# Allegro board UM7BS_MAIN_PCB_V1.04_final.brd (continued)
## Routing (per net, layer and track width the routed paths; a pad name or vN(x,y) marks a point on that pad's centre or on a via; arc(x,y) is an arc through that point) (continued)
+V3.3S_MSATA: length 25
  LAY3 w0.762: v2(70.73,33.09) 74.73,37.08 74.73,54.17 76.15,55.59 v2(76.41,55.59)
+V5_AVDD: length 25.3
  LAY3 w0.305: v1(24.9,24.75) 26.86,22.78 v1(33.87,22.78)
  LAY3 w0.406: v1(24.9,24.75) 20.82,24.75 19.86,25.71 v1(19.86,26.75)
  BOTTOM w0.178: 20.96,32.48 21.52,33.04 U25.26
  BOTTOM w0.254: R355.2 v1(33.87,22.78)
  BOTTOM w0.305: R349.2 v1(24.9,24.75)
  BOTTOM w0.406: C370.1 20.54,31.33 C369.2 20.96,31.47 20.96,32.48
  BOTTOM w0.508: C370.1 19.6,28.92 FB8.1 19.62,27.54 D43.N v1(19.86,26.75)
+V5_PVDD: length 8.5
  LAY3 w0.406: v1(24.38,39.02) 24.84,38.56 27.84,38.56 v1(28.15,38.87)
  BOTTOM w0.178: U25.41 24.23,38.44 ; U25.46 26.23,38.02 27.02,38.82 27.02,38.91
  BOTTOM w0.254: 24.23,38.44 23.76,38.91 23.76,39.32 24.03,39.6 C382.2
  BOTTOM w0.406: C382.2 24.38,39.29 v1(24.38,39.02)
+V5A: length 202.8
  TOP w0.178: U11.24 160.84,17.78 ; U11.11 156.63,21.19 ; U11.57 160.84,26.63 ; U11.21 159.64,17.77
  TOP w0.203: R174.1 181.89,95.57 v1(182.24,95.92) ; R492.1 60.95,11.85 ; 41.26,19.8 41.26,20.73 41.62,21.09 41.62,21.94 41.11,22.45 R487.1
  TOP w0.254: v1(147.22,47.73) 147.34,47.61 C11.2 150.99,47.27 151.63,46.62 U3.4 ; v1(138.46,54.12) 138.92,54.59 150.43,54.59 151.38,55.54 v1(151.38,56.05)
  TOP w0.305: 156.63,21.19 156.35,21.19 ; v1(160.91,16.95) 160.84,17.03 160.84,17.78 ; 160.84,26.63 v1(160.66,26.81) ; v1(167.41,90.98) 167.41,90.56 R171.2 ; R177.1 v1(168.18,92.56) ; 159.64,17.77 v1(159.64,16.98)
  TOP w0.508: v1(124.62,56.86) 136.67,56.86 137.79,57.98 137.79,71.86 137,72.65
  LAY3 w0.305: v1(122.54,65.38) 123.56,65.38 125.41,67.23 130.57,67.23 v1(133.77,70.43) ; v2(135.75,75.36) 136.87,75.36 138.31,76.8 151.11,76.8 v1(152.26,75.64)
  LAY4 w0.305: 136.15,74.22 136.58,73.79 136.58,63.29 139.44,60.43 139.44,55.8 145.91,49.33 145.91,48.78 146.96,47.73 v1(147.22,47.73)
  BOTTOM w0.203: U10.14 121.6,63.47 122.54,64.41 v1(122.54,65.38)
  BOTTOM w0.254: v1(152.26,75.64) 152.26,74.94 152.75,74.46 158.31,74.46 159.88,72.89 159.88,71.34 161.08,70.14 161.9,70.14 C2836.1 163.25,68.79 163.38,68.79 ; v1(138.46,54.12) 138.46,54.44 135.98,56.92
  BOTTOM w0.305: v1(151.38,56.05) C436.1 151.38,53.77 U53.10 ; v1(152.26,75.64) 152.95,76.32 155.69,76.32 161.25,81.89 161.88,81.89 164.72,84.73 164.72,88.29 v1(167.41,90.98) 167.41,91.78 v1(168.18,92.56) 171.54,95.92 v1(182.24,95.92) ; 163.38,68.79 U2525.10
  BOTTOM w0.381: v1(160.66,26.81) 160.08,26.24 C218.1 158.01,26.06 157.83,26.24 157.04,26.24 156.76,25.96 156.76,23.22 156.17,22.63 155.71,22.63 155.33,22.25 155.33,21.03 ; 107.43,59.94 D4.1 107.43,64.76 C180.1
  BOTTOM w0.508: R180.1 124.51,56.97 v1(124.62,56.86)
  vias: v1(155.25,19.95) v1(155.63,20.36) v1(156.04,20.77) v1(159.64,16.34) v1(160.91,16.34) v2(13.19,80.45) v2(14.08,80.45) v2(41.23,16.09) v2(45.85,37.42) v2(46.61,37.42) v2(47.37,37.42) v2(53.05,87.7) v2(53.81,87.7) v2(61.22,11.11) v2(133.97,76.63) v2(133.97,75.36) v2(134.86,76.63) v2(134.86,75.36) v2(135.75,76.63) v2(143.76,21.43) v2(143.77,22.39) v2(144.53,22.39) v2(144.53,21.43)
+V5A_LDO: length 41.7
  TOP w0.178: C182.2 160.13,27.67 160.67,27.67 161.24,27.11 U11.56 ; v1(154.84,22.47) 154.89,22.52 156,22.52 156.13,22.39 U11.8 ; U11.38 166.23,21.19
  TOP w0.203: 166.23,21.19 166.46,20.96 166.82,20.96 v1(167.04,20.74)
  TOP w0.508: C182.2 159.05,28.09 v1(159.05,27.7)
  LAY4 w0.508: v1(168.88,27.42) 167.8,27.42 164.3,23.92 160.32,23.92 158.94,25.29 158.94,27.59 v1(159.05,27.7)
  BOTTOM w0.381: v1(159.05,27.7) 159.05,28.2 158.78,28.48 156.85,28.48 154.64,26.26 154.64,23.94 154.2,23.5 C212.2 154.79,22.52 v1(154.84,22.47)
  BOTTOM w0.508: v1(167.04,20.74) C215.1 168.08,21.11 168.08,22.89 168.88,23.69 v1(168.88,27.42)
+V5S: length 91.6
  TOP w0.381: R2.1 132.94,13.08 132.68,13.34 FB24.2
  TOP w0.508: v2(134.55,17.31) 134.55,16.58 132.68,14.71 FB24.2
  LAY3 w0.203: v1(42.71,66.55) 42.71,68.92 45.89,72.1 45.89,76.62 50.91,81.65 v1(51.73,81.65)
  LAY4 w0.508: v2(138.65,42.35) 136.86,40.56 136.86,33.33 134,30.47 134,24.9 133.08,23.99 133.08,18.77 v2(134.55,17.31)
  BOTTOM w0.203: v1(42.71,66.55) 43.01,66.85 R418.1 R419.1
  BOTTOM w0.305: 110.67,82.98 R223.1 R225.1
  BOTTOM w0.508: 139.82,69.46 139.29,68.93 139.29,65.51 137.93,64.14 137.93,59.33 139.1,58.16 139.1,42.8 v2(138.65,42.35) ; FB8.2 18.12,28.06 D43.P 17.36,26.4 C360.1 18.01,25.07 v1(17.74,24.8)
  vias: v2(30.41,45.27) v2(30.91,83.21) v2(31.8,83.21) v2(89.59,67.32) v2(90.64,67.32) v2(106.29,84.04) v2(107.05,84.04) v2(141.24,84.8) v2(141.24,84.04) v2(142,84.8) v2(142,84.04) v2(150.55,71.85) v2(150.55,70.96) v2(150.55,70.07) v2(151.31,71.85) v2(151.31,70.96) v2(151.31,70.07)
+V5S_HDD:
  vias: v2(98.42,54.95) v2(99.31,54.97)
+V15A: length 79.3
  TOP w0.305: v1(109.18,76.33) 108.59,75.75 108.59,73.12 108.89,72.82 v1(108.89,65.79)
  BOTTOM w0.305: v1(108.89,65.79) 112.19,65.79 C179.1 ; C179.1 116.02,65.1 117.21,66.3 117.21,71.15 121.48,75.41 129.97,75.41 131.98,77.43 146.96,77.43 150.47,73.92 155.85,73.92 156.62,73.15 R215.1 158.93,71.89 R216.1 ; C179.1 D5.2 ; R221.1 113.06,74.94 R220.1 112.66,74.93 112.54,75.05 111.2,75.05 110.48,75.77 109.74,75.77 v1(109.18,76.33)
+VCCCFIOAZA: length 6.8
  BOTTOM w0.381: v1(184.65,51.25) 184.67,51.25 C112.1 185.51,50.71 186.21,50.02 186.21,48.32 185.68,47.8 R137.2 R138.2
+VCCDPYCSIAON_1P24: length 11.2
  LAY4 w0.305: v1(178.79,69.17) 178.45,69.17 178.01,69.62 177.55,69.62 177.26,69.33 176.24,69.33 v1(176.17,69.41)
  BOTTOM w0.381: v1(178.79,69.17) 178.96,69.17 179.44,69.66 C81.2 179.47,70.05 R130.2 ; v1(176.17,69.41) 176.17,68.39 175.48,67.71 175.48,66.46 175.73,66.21 177.88,66.21 R136.2
+VCCPADHSICAON_1P24: length 2.2
  TOP w0.203: v1(177.77,69.03) 177.77,69.08 U1.M41
  BOTTOM w0.381: R139.2 177.77,68.8 v1(177.77,69.03) 177.77,69.22 R131.2
+VCCPADSSICAON_1P24: length 4.1
  TOP w0.203: U1.P41 178.63,69.81 v1(178.79,69.81)
  BOTTOM w0.381: R142.2 178.45,72.3 178.45,71.72 R132.2 178.06,70.54 v1(178.79,69.81)
+VDDI_EMMC: length 6.2
  BOTTOM w0.076: 179.46,31.52 179.46,30.88 U8.K2 179.96,30.86 179.96,31.53
  BOTTOM w0.381: C143.1 182.09,34.48 179.68,32.06 179.68,31.81
AGND: length 175.4
  TOP w0.203: v1(18.15,33.19) 17.89,33.45 17.89,35.83 18.2,36.15 18.74,36.15 19.38,35.51 19.38,34.28 v1(21.66,32) 23.63,32 24.09,31.53 32.15,31.53 33.95,29.72 37.11,29.72 37.63,29.2 37.63,27.53 36.8,26.7 35.87,26.7 35.4,27.17 30.98,27.17 30.04,26.24 J3.5 ; v1(24.32,25.87) 24.32,25.87 23.57,25.87 22.98,25.28 21.74,25.28 21.29,25.73 21.29,26.22 20.19,27.33
  TOP w0.254: C397.2 24.66,28.62 24.91,28.37 26.29,28.37 26.55,28.62 v1(26.55,28.7)
  TOP w0.305: C397.2 24.65,28.7 R357.2 ; C399.2 21.95,25.87 v1(22.01,25.81) ; CN7.E2 59.84,8.14 58.54,9.44 CN7.1 58.54,11.17 58.28,11.43 54.91,11.43 51.83,8.35 33.61,8.35 26.27,15.69 26.27,26.46 v1(26.14,26.59) 26.16,26.6 26.16,27.04 25.84,27.36 25.3,27.36 24.92,26.99 24.92,25.88 ; v1(18.15,33.19) 20.59,30.75 v1(20.59,29.72) 20.19,29.32 20.19,27.33 ; C398.2 32.27,29.25 J3.2 ; 24.92,25.88 25.4,25.4 25.4,15.33 33.25,7.48 52.19,7.48 54.62,9.91 56.47,9.91 57.05,9.34 57.05,8.69 B1.2 ; 24.92,25.88 24.34,25.88 v1(24.32,25.87) ; R356.2 22.87,30.15 C396.2 22.87,30.22 22.23,30.86 v1(21.95,30.86)
  BOTTOM w0.178: U25.38 23.03,38.04 22.71,38.36 22.05,38.36 v1(21.94,38.25) ; v1(21.66,32) 21.65,32 21.44,32.2 21.44,32.46 21.63,32.64 U25.25
  BOTTOM w0.305: Q36.2 v1(27.69,25.03) ; R338.2 26.7,28.86 v1(26.55,28.7) ; C376.1 18.2,41.39 v1(17.63,40.81) ; C393.2 v1(30.29,19.88) ; C394.2 v1(37.5,19.41)
  BOTTOM w0.381: C370.2 v1(18.4,30.39) ; v1(20.83,41.22) 20.83,41.16 21.47,40.52 C372.2 22.2,39.5 C371.1 ; C369.1 20.82,29.96 v1(20.59,29.72) ; C365.1 18.44,32.9 v1(18.15,33.19) 18.14,33.2 C363.2
  vias: v1(20.4,43.12) v1(20.41,42.58) v1(23.73,25.42)
AVDD2: length 5.4
  BOTTOM w0.178: 23.83,38.23 U25.40
  BOTTOM w0.254: 23.83,38.23 23.15,38.91 C371.2
  BOTTOM w0.381: C371.2 23.15,40.05 C372.1
  BOTTOM w0.508: C372.1 22.99,40.25 FB11.1 FB10.1
AVDD33: length 3.8
  BOTTOM w0.203: U95.4 76.81,94.37 C702.2
  BOTTOM w0.305: FB20.1 77.36,91.62 C703.1 77.36,92.82 C702.2
AVDD33_REG: length 8.7
  BOTTOM w0.203: U22.34 124.3,37.2 124.51,37 124.51,36.8 U22.35
  BOTTOM w0.381: C336.1 125.37,35.94 124.51,36.8
  BOTTOM w0.508: C336.1 125.92,35.65 126.27,35.29 128.17,35.29 128.55,35.67 C335.2 R299.1
GND: length 1635.2
  TOP w0.102: v1(195.34,76.1) 194.88,75.8 U1.BG53
  TOP w0.152: 178.96,64.88 U1.U32 ; U1.U32 179.35,65.28 ; U1.U32 179.67,64.88 ; 185.12,69.92 U1.AH42 ; U1.AH42 184.73,70.23 ; U1.AH42 185.12,70.53 ; U1.AH42 185.42,70.23 ; 184.06,61.49 U1.AF24 183.74,61.09 ; U1.U29 179.35,63.76 ; U1.U29 179.67,63.37 ; U1.U29 178.96,63.37 ; 181,51.7 U1.Y4 ; U1.Y4 181.53,51.47 ; U1.Y4 180.85,51.47 ; U1.AN29 187.98,63.77 U1.AN30 ; U1.AN29 187.98,63 ; U1.AN29 187.66,63.37 ; 187.98,68.23 U1.AN38 188.3,67.92 ; 185.12,69.13 U1.AH41 ; U1.AH41 184.73,69.51 ; U1.AH41 185.31,69.51 185.41,69.62 ; U1.AH41 185.12,69.82 ; 188.03,53.19 U1.AP9 ; U1.AP9 188.03,53.95 ; U1.AP9 188.33,53.57 ; 191,60.78 U1.AY24 ; U1.AY24 190.62,61.16 ; U1.AY24 191.3,61.16 ; 175.25,64.06 U1.J30 ; U1.J30 175.93,64.06 ; U1.J30 175.63,64.44 ; 178.47,64.67 U1.P32 ; U1.P32 178.09,65.05 ; U1.P32 178.47,65.43 ; U1.P32 178.78,65.05 ; U1.AE48 183.97,72.72 ; U1.A5 171.52,51.44 ; U1.A5 171.85,51.77 ; U1.A5 171.85,51.11 ; 175.63,69.54 U1.J42 ; U1.J42 175.25,69.92 ; U1.J42 175.63,70.31 ; U1.J42 175.93,69.92 ; 180.55,69.65 180.42,69.51 U1.V41 180.26,69.81 ; 185.42,54.28 U1.AH10 185.12,54.66 ; 179.38,71.98 179.76,71.98 U1.U46 179.79,72 180.14,72 ; 180.92,60.73 U1.Y22 181.24,60.33 ; 186.41,51.47 U1.AK4 185.73,51.47 ; 181.23,56.03 U1.Y14 ; U1.Y14 181.23,56.79 ; U1.Y14 181.53,56.41 ; U1.Y14 180.85,56.41 ; U1.AH44 184.81,70.94 ; U1.AH44 185.12,70.63 ; U1.AH44 185.12,71.24 ; 176.9,68.93 U1.M40 ; U1.M40 176.82,68.54 ; U1.M40 177.22,68.65 ; U1.M40 177.62,68.54 ; 191.97,74.17 U1.BB50 191.67,73.87 ; 180.52,62.96 U1.Y29 ; U1.Y29 181.33,62.96 ; U1.Y29 180.92,63.06 ; 189.13,50.54 U1.AU3 ; U1.AU3 189.79,50.54 ; U1.AU3 189.5,50.91 ; U1.AN30 188.3,64.12 ; U1.AN30 U1.AM30 187.2,64.52 ; U1.AN30 187.98,64.46 ; U1.AC29 182.81,63.37 ; U1.AC29 182.49,63.76 ; U1.AC29 182.1,63.37 ; U1.AC29 182.49,62.97 ; 185.12,55.37 U1.AH12 185.42,54.99 ; U1.Y45 181.53,71.65 ; U1.Y45 181.23,72.03 ; U1.Y45 181.23,71.27 ; U1.U38 179.67,67.92 ; U1.U38 179.35,68.31 ; U1.U38 178.96,67.92 ; 195.48,54.55 U1.BJ11 ; U1.BJ11 195.48,55.11 ; U1.BJ11 v1(196.11,54.83) ; 180.53,59.57 U1.Y21 ; U1.Y21 181.24,59.57 ; U1.Y21 180.92,59.97 ; U1.Y21 180.92,59.18 ; 181.72,75.02 U1.AA53 ; U1.AA53 182.08,75.42 ; U1.AA53 181.72,75.82 ; U1.T47 179.31,72.74 ; U1.T47 179.31,71.98 ; U1.T47 179,72.36 ; U1.BG49 194.31,73.49 ; U1.BG49 194,73.19 ; U1.BG49 194.31,72.88 ; U1.BC16 192.42,57.65 ; U1.BC16 192.04,57.27 ; U1.BC16 192.72,57.27 ; U1.BC16 192.42,56.89 ; U1.A7 171.52,52.86 ; U1.AM50 187.05,73.44 ; U1.AM50 186.75,73.74 ; U1.AM50 187.3,73.99 187.81,73.99 U1.AP50 188.12,73.74 v1(188.49,74.11) ; 179.78,68.87 U1.U40 ; 173.19,54.3 173.19,54.3 U1.D10 173.8,54.3 ; U1.AB47 182.6,72.36 ; U1.AB47 182.22,72.03 ; U1.AB47 182.22,72.74 ; U1.M45 177.65,71.65 ; U1.M45 177.34,71.27 ; U1.M45 176.96,71.65 ; U1.M45 177.34,72.03 ; 182.22,56.08 U1.AB13 182.52,55.7 ; U1.P22 178.47,60.55 ; U1.P22 178.78,60.17 ; U1.P22 U1.N22 178.16,60.57 ; U1.BG38 194.4,68.24 ; U1.BG38 194.4,67.66 ; U1.BG38 194.69,67.95 ; U1.BF32 193.8,65.35 ; 179.82,64.88 U1.V32 180.14,64.49 ; U1.AM38 187.38,67.92 187.5,68.04 ; U1.AM38 187.2,68.23 ; U1.AM38 187.05,67.92 186.9,68.07 ; 191.59,51.35 U1.BB4 ; U1.BB4 191.97,51.73 ; U1.BB4 192.28,51.35 ; U1.U25 179.76,61.44 ; U1.U25 179.04,61.85 ; U1.U25 178.95,62.25 ; U1.U25 178.95,61.44 ; U1.AY45 191.29,71.65 ; U1.AY45 190.98,71.34 ; U1.AY45 190.98,71.95 ; U1.T14 179.61,56.41 ; U1.T14 179.31,56.03 ; U1.T14 178.92,56.41 ; U1.T14 179.31,56.79 ; 193.8,60.55 U1.BF22 193.5,60.17 ; v1(182.88,59.2) 183.26,59.57 U1.AD21 182.87,59.17 ; 193.97,63.07 U1.BF28 193.66,62.77 ; 186.8,61.09 U1.AM24 ; U1.AM24 187.2,61.49 ; U1.AM24 187.51,61.09 ; U1.AM24 187.2,60.7 ; 186.01,62.2 U1.AK27 ; U1.AK27 186.82,62.2 ; U1.AK27 186.82,63.01 ; U1.AJ25 185.63,62.24 ; U1.AJ25 185.23,61.85 ; U1.AJ25 185.63,61.46 ; 172.24,66.61 U1.B36 ; U1.B36 172.53,66.98 ; U1.B36 172.24,67.35 ; U1.B36 171.87,66.98 ; 181.82,73.35 U1.AB50 ; U1.AB50 181.82,74.14 ; U1.AB50 182.62,73.35 ; 178.42,58.72 U1.P19 178.12,58.34 ; 176.75,69.04 U1.L41 176.75,69.74 ; 186.14,68.19 U1.AK38 186.45,67.92 186.69,68.15 ; U1.BG47 194.38,72.47 ; U1.BG47 194.38,71.86 ; U1.BG47 194.07,72.16 ; 182.81,51.22 U1.AD4 ; U1.AD4 182.81,52.01 ; U1.AD4 183.2,51.28 ; U1.AD4 183.51,51.61 ; U1.AD4 182.88,51.61 ; 186.41,73.74 U1.AK50 186.11,73.44 ; U1.AW35 190.64,66.19 ; v1(173.25,66.49) 173.25,66.49 U1.E35 173.85,66.87 ; U1.AJ16 185.63,57.69 ; U1.AJ16 185.23,57.3 ; U1.AJ16 185.95,57.3 ; U1.AJ16 185.63,56.91 ; 195.08,62.61 U1.BJ27 ; U1.BJ27 195.81,62.61 ; U1.BJ27 195.48,62.3 ; U1.AE43 183.64,70.61 183.33,70.61 ; U1.AB14 182.22,56.79 ; U1.AB14 181.84,56.41 ; U1.AB14 182.52,56.41 ; 174.56,66.84 U1.F35 174.56,66.17 ; U1.AF47 184.14,72.67 ; U1.AF47 184.14,72.05 ; U1.AF47 184.45,72.36 ; 172.89,68.44 U1.C39 172.6,68.07 ; U1.AF25 184.06,62.24 ; 190.64,58.42 U1.AW19 190.64,59.08 ; 194.74,62.24 U1.BG27 ; U1.BG27 194.37,62.61 ; U1.BG27 195.03,62.61 ; 191.3,62.13 U1.AY26 191.39,61.74 ; 179.68,59.45 179.56,59.57 U1.U21 ; U1.AN1 187.83,49.79 ; U1.AN1 187.55,49.39 ; U1.AN1 187.55,50.19 ; U1.AN1 187.2,49.79 ; U1.AK44 186.41,70.94 ; U1.AK44 185.8,70.94 ; U1.AK44 186.11,70.63 ; U1.AK44 186.11,71.24 ; U1.AY22 191,60.55 ; U1.AY22 191,59.79 ; U1.AY22 191.3,60.17 ; U1.AY22 190.62,60.17 ; 177.76,64.67 U1.N32 ; U1.N32 178.07,65.05 ; U1.N32 177.76,65.43 ; U1.N32 177.38,65.05 ; 185.23,58.06 U1.AJ18 ; U1.AJ18 185.95,58.06 ; U1.AJ18 185.63,58.45 ; U1.V25 180.54,61.44 ; U1.V25 180.46,61.85 ; U1.V25 180.54,62.25 ; U1.V25 179.73,61.44 ; U1.AC35 182.9,65.99 ; U1.AC35 182.17,66.4 ; U1.AC35 182.09,66.8 ; 182.49,56.91 U1.AC16 182.81,57.3 ; 172.33,49.79 U1.C1 172.72,49.55 172.55,49.39 ; U1.C36 172.65,66.98 ; U1.C36 172.94,66.61 ; U1.C36 172.94,67.35 ; 185.12,53.19 U1.AH9 ; U1.AH9 184.73,53.57 ; U1.AH9 185.12,53.95 ; U1.AH9 185.42,53.57 ; U1.Y10 181.23,54.66 ; U1.Y10 181.53,54.28 ; U1.Y10 180.85,54.28 ; U1.K34 176.64,66.02 ; U1.K34 175.96,66.02 ; U1.K34 176.34,65.64 ; U1.BJ15 v1(196.11,56.78) ; U1.BJ15 195.48,56.5 ; U1.BJ15 195.48,57.09 ; U1.D32 U1.F32 174.51,65.05 ; U1.BG19 195.03,58.72 ; U1.BG19 194.74,59.09 ; U1.BG19 194.74,58.35 ; v1(175.91,64.58) 176.34,64.16 U1.K30 175.96,64.06 ; U1.P42 178.33,70.61 ; U1.P42 178.64,70.23 ; U1.P42 177.95,70.23 ; 181.84,54.28 U1.AB10 ; U1.AB10 182.22,53.9 ; U1.AB10 182.52,54.28 ; U1.AB10 182.22,54.66 ; U1.AT36 188.86,67.28 ; U1.AT36 188.86,66.66 ; U1.AT36 188.56,66.97 ; U1.AB6 182.22,52.53 ; U1.AB6 182.52,52.14 ; U1.AB6 181.84,52.14 ; 188.64,50.88 U1.AT3 ; U1.AT3 189.3,50.88 ; U1.AT3 189.01,50.51 ; U1.J38 175.63,68.32 ; U1.J38 175.93,67.94 ; U1.J38 175.63,67.56 ; U1.J38 175.25,67.94 ; U1.BJ19 195.48,59.02 ; U1.BJ19 v1(195.98,58.72) ; U1.BJ19 195.48,58.39 ; 180.11,51.8 179.79,51.8 U1.U5 ; 172.96,71.78 U1.C47 ; U1.C47 172.96,72.54 ; U1.C47 173.26,72.16 ; U1.J22 175.25,60.54 v1(175.25,60.64) ; U1.G22 174.64,60.44 v1(174.64,60.64) ; U1.AY9 191.29,53.57 ; U1.AY9 190.6,53.57 ; U1.AY9 190.98,53.95 ; U1.AH13 185.12,55.39 ; 174.53,64.06 U1.G30 ; U1.G30 175.22,64.06 ; U1.G30 174.92,63.68 ; U1.G30 174.92,64.44 ; U1.AW13 190.89,55.86 ; U1.AW13 190.58,55.48 ; U1.AW13 190.58,56.24 ; 175.96,65.05 U1.K32 ; U1.K32 176.64,65.05 ; U1.K32 176.34,65.43 ; U1.BF12 193.5,55.29 ; U1.BF12 193.8,55.67 ; U1.BF12 193.8,54.91 ; U1.AN43 187.25,70.58 ; 195.08,60.66 U1.BJ23 ; U1.BJ23 195.48,60.97 ; U1.BJ23 195.76,60.66 ; U1.BJ23 195.48,60.37 ; 186.02,57.3 U1.AK16 ; U1.AK16 186.41,57.69 ; U1.AK16 186.41,56.91 ; U1.AK16 186.73,57.3 ; 186.02,61.85 U1.AK25 ; U1.AK25 186.41,62.24 ; U1.AK25 186.41,61.46 ; U1.AN49 187.25,73.43 ; U1.AT18 189.17,58.25 ; U1.AT18 188.86,57.86 ; U1.AT18 188.86,58.63 ; U1.AT18 188.48,58.25 ; U1.AT19 188.94,58.72 ; U1.AT19 189.22,59.06 ; U1.AT19 189.22,58.39 ; U1.AF10 184.18,54.28 v1(184.55,53.91) ; U1.AF10 184.14,53.93 ; U1.AF10 184.54,53.88 ; 193.97,62.14 U1.BF26 ; U1.BF26 193.66,62.45 ; U1.BF26 193.66,61.76 ; U1.BG34 194.4,66.3 ; U1.BG34 194.69,66.01 ; U1.BG34 194.4,65.72 ; 171.9,50.22 U1.B2 172.28,49.84 ; 182.02,67.92 U1.AA38 181.71,68.31 ; 194.03,62.24 U1.BF27 ; U1.BF27 194.03,62.98 ; U1.BF27 194.33,62.61 ; U1.BF27 193.74,62.61 ; 178.01,54.19 178.09,54.28 U1.P10 178.33,53.95 ; 173.54,71.93 U1.E46 ; U1.E46 174.23,71.93 ; U1.E46 173.92,71.55 ; U1.E46 173.92,72.31 ; U1.BC40 192.42,68.63 ; U1.BC40 192.11,68.93 ; U1.BC40 192.72,68.93 ; 194.6,49.34 U1.BH1 195.05,49.41 ; U1.AN3 187.85,50.54 ; U1.AN3 187.55,50.91 ; U1.AN3 187.19,50.54 ; U1.Y24 181.33,60.69 ; U1.Y24 180.52,61.5 ; U1.Y24 181.33,61.5 ; U1.Y24 181.24,61.09 ; 180.14,68.31 U1.V38 179.82,67.92 ; U1.AT51 189.01,74.63 ; U1.AT51 188.72,74.34 ; U1.AT51 189.3,74.34 ; 179.46,72.71 179.77,72.71 U1.U48 179.78,72.71 180.12,72.71 ; U1.AN25 188.39,61.44 ; U1.AN25 187.98,61.51 ; U1.AN25 187.58,61.44 ; 189.9,64.06 U1.AV30 190.59,64.06 ; 185.12,72.05 U1.AH47 ; U1.AH47 184.81,72.36 ; U1.AH47 185.12,72.67 ; 187.2,63 U1.AM27 186.88,62.61 ; U1.AE8 183.95,53.21 ; U1.AN33 187.98,65.96 ; 187.08,55.32 U1.AM13 186.77,55.7 ; 189,53.19 U1.AT9 ; U1.AT9 189.31,53.57 ; U1.AT9 189,53.95 ; U1.AT9 188.62,53.57 ; 180.26,69.85 U1.V42 180.56,70.23 ; 192.96,49.39 U1.BD1 193.29,49.79 ; U1.Y19 180.92,59.18 ; U1.Y19 180.52,59.22 ; U1.Y19 181.33,59.22 ; U1.AB4 182.52,51.47 ; U1.AB4 181.84,51.47 ; U1.AB4 182.22,51.85 ; 179.35,67.55 U1.U36 179.04,67.16 ; 191.35,62.23 U1.BA27 ; U1.AK7 185.8,52.86 ; U1.AK7 186.11,52.47 ; U1.AK7 186.11,53.24 ; 183.67,67.92 U1.AF38 ; U1.AF38 183.68,67.54 v1(183.67,67.54) 183.29,67.16 U1.AD36 183.28,67.16 182.97,67.46 ; U1.AF38 183.66,68.32 ; 187.98,59.18 U1.AN21 188.3,59.57 ; 185.8,68.8 U1.AK40 186.11,68.5 ; U1.AE6 183.83,52.16 ; U1.AY20 191.3,59.2 ; U1.AY20 190.62,59.2 ; U1.AY20 191,59.58 ; 179.18,59.91 179.35,59.73 U1.U21 ; 194.14,73.77 U1.BF50 193.83,73.47 ; 190.98,52.47 U1.AY7 ; U1.AY7 191.29,52.86 ; U1.AY7 190.6,52.86 ; U1.AY7 190.98,53.24 ; U1.AJ3 185.61,50.91 ; U1.AJ3 185.9,50.54 ; U1.AJ3 185.24,50.54 ; U1.AT45 189,71.95 ; U1.AT45 189,71.34 ; U1.AT45 188.7,71.65 ; U1.BG36 194.69,66.98 ; U1.BG36 194.4,67.27 ; U1.BG36 194.4,66.69 ; 182.52,54.99 U1.AB12 182.22,55.37 ; 173.71,74.25 U1.E51 ; U1.E51 174.39,74.25 ; U1.E51 174.09,73.87 ; 191.29,72.36 U1.AY47 190.98,72.05 ; 177.65,73.74 U1.M50 176.96,73.74 ; U1.BJ7 v1(196.11,52.99) ; U1.BJ7 195.48,52.67 ; U1.BJ7 195.48,53.38 ; 192.78,58.37 U1.BD19 192.78,59.03 ; 180.53,57.3 U1.Y16 ; U1.Y16 181.24,57.3 ; U1.Y16 180.92,57.69 ; U1.Y16 180.92,56.91 ; 191.35,59.03 U1.BA19 ; 194.69,59.21 U1.BG20 194.4,59.57 ; 187.67,51.47 U1.AP4 188.36,51.47 ; 178.95,57.65 U1.U18 ; U1.U18 179.35,57.77 ; U1.U18 178.95,58.46 ; U1.U18 179.07,58.06 ; U1.AH14 185.12,56.87 v1(185.18,56.94) ; U1.BG35 194.74,66.2 ; U1.BG35 194.45,66.49 ; U1.BG35 194.74,66.79 ; U1.BG35 195.03,66.49 ; U1.AN24 187.98,61.49 ; U1.AN24 187.59,61.09 ; U1.AN24 187.98,60.7 ; U1.AN24 188.3,61.09 ; 194.4,64.36 U1.BG30 194.69,64.07 ; U1.D38 173.53,68.32 ; U1.D38 173.53,67.56 ; U1.D38 173.84,67.94 ; 194.4,55.92 U1.BG14 ; U1.BG14 194.69,56.29 ; U1.BG14 194.4,56.66 ; 189.21,74.68 U1.AU51 189.5,74.39 ; 189.93,59.05 U1.AV19 ; 181.71,63 U1.AA27 182.02,62.61 ; U1.AK47 186.11,72.67 ; U1.AK47 186.41,72.36 ; U1.AK47 185.8,72.36 ; U1.AK47 186.11,72.05 ; 175.27,66.82 U1.H35 175.27,66.15 ; 190.96,74.63 U1.AY51 191.25,74.34 ; 193.08,62.61 U1.BD27 ; 187.98,56.91 U1.AN16 188.3,57.3 ; 189.14,49.79 U1.AU1 ; U1.AU1 189.78,49.79 ; U1.AU1 189.5,49.39 ; U1.AU1 189.5,50.19 ; 186.88,57.3 U1.AM16 187.2,56.91 ; 175.22,63.08 U1.G28 174.92,63.46 ; 181.23,68.42 U1.Y40 ; U1.Y40 180.85,68.8 ; U1.Y40 181.23,69.18 ; U1.Y40 181.53,68.8 ; U1.U45 179.78,71.3 179.9,71.3 U1.V44 179.9,70.58 179.78,70.58 U1.U43 179.78,70.58 179.48,70.58 ; 175.97,73.74 U1.K50 176.66,73.74 ; U1.F5 174.67,52.04 ; 192.42,55.9 U1.BC14 ; U1.BC14 192.42,56.66 ; U1.BC14 192.04,56.28 ; U1.BC14 192.72,56.28 ; 190.89,69.36 U1.AW41 190.58,69.05 ; 187.86,72 U1.AN46 187.25,72 ; U1.G12 175.22,55.29 ; U1.U21 179.76,59.17 ; U1.U21 178.95,59.17 ; U1.U21 179.35,59.25 ; U1.K16 176.08,57.27 ; 176.69,66.19 U1.L35 176.69,66.83 ; 190.29,60.78 U1.AV24 ; U1.AV24 189.9,61.16 ; U1.AV24 190.59,61.16 ; U1.D40 173.53,69.31 ; U1.D40 173.84,68.93 ; U1.D40 173.53,68.55 ; 193.52,51.44 U1.BF4 193.83,51.83 ; 194.44,49.39 U1.BG1 194.03,49.79 ; 186.67,64.63 186.42,64.88 U1.AK32 186.82,64.48 ; U1.AY30 U1.BA30 192.01,64.06 ; U1.AY30 191,64.36 ; U1.AY30 190.69,64.06 ; U1.K36 176.64,66.97 ; U1.K36 175.96,66.97 ; U1.K36 176.34,67.35 ; 183.99,53.92 U1.AE9 183.35,53.92 ; U1.BG16 194.4,57.63 ; U1.BG16 194.69,57.26 ; U1.BG16 194.4,56.89 ; v1(173.25,63.57) 172.94,63.87 U1.C30 ; v1(171.59,67.99) 171.59,68.18 U1.A39 171.85,68.08 ; 192.43,53.92 U1.BC10 ; U1.BC10 192.43,54.68 ; U1.BC10 192.74,54.3 ; 192.42,68.25 U1.BC38 192.11,67.94 ; U1.AM42 187.08,70.53 ; U1.AM42 187.08,69.92 ; U1.AM42 186.77,70.23 ; U1.AJ1 185.61,50.19 ; U1.AJ1 185.89,49.79 ; U1.AJ1 185.61,49.39 ; U1.U42 179.78,69.88 180.13,69.88 ; U1.Y38 180.92,68.26 ; U1.Y38 181.33,68.32 ; U1.Y38 180.52,68.32 ; U1.H8 175.67,53.48 ; 181.23,53.19 U1.Y9 ; U1.Y9 180.85,53.57 ; U1.Y9 181.23,53.95 ; U1.Y9 181.53,53.57 ; U1.U33 179.67,65.64 ; U1.U33 178.96,65.64 ; U1.U33 179.35,66.03 ; U1.AB42 182.22,70.61 ; U1.AB42 182.22,69.85 ; U1.AB42 181.84,70.23 ; U1.AB42 182.52,70.23 ; 188.03,71.34 U1.AP45 188.03,71.95 ; U1.AK45 186.11,71.95 ; U1.AK45 185.8,71.65 ; U1.AK45 186.11,71.34 ; U1.AK45 186.41,71.65 ; 175.98,66.87 U1.J35 175.98,66.14 ; U1.BJ43 195.48,70.66 ; U1.BG24 194.69,61.15 ; U1.BG24 194.4,60.78 ; U1.BG24 194.4,61.52 ; U1.BE35 193.83,66.34 ; 192.42,63.39 U1.BC28 192.11,63.08 ; U1.U30 179.35,64.52 ; U1.U30 178.96,64.12 ; U1.U30 179.67,64.12 ; U1.BB19 192.06,58.35 ; U1.C3 173.35,50.96 ; 186.63,63.13 186.41,63.35 U1.AK29 186.82,62.96 ; U1.K45 176.66,71.65 ; U1.K45 176.35,72.03 ; U1.K45 176.35,71.27 ; 180.14,59.18 U1.V21 180.46,59.57 ; 182.1,67.92 U1.AC38 ; U1.AC38 182.49,68.31 ; U1.AC38 182.81,67.92 ; 175.27,58.42 U1.H19 ; U1.AF27 184.46,62.2 ; 181.39,57.3 U1.AA16 181.71,56.91 ; 178.09,66.97 U1.P36 ; U1.P36 178.47,67.35 ; U1.P36 178.47,66.59 ; U1.P36 178.78,66.97 ; 190.59,50.88 U1.AY3 ; U1.AY3 190.96,50.51 ; U1.AY3 191.25,50.88 ; U1.K12 176.02,55.29 ; 189.73,56.28 U1.AV14 ; U1.AV14 190.42,56.28 ; U1.AV14 190.11,56.66 ; 184.84,61.46 U1.AG25 ; U1.AG25 184.84,62.24 ; U1.AG25 184.45,61.85 ; U1.AV40 190.11,68.63 ; 192.43,71.22 U1.BC44 192.74,70.92 ; 177.84,74.31 U1.N51 ; 178.12,66.11 U1.P35 ; U1.P35 178.12,66.88 ; U1.P35 178.42,66.49 ; U1.BB27 192.06,62.91 ; 187.43,51.47 U1.AM4 186.75,51.47 ; 187.69,75.1 U1.AN53 ; 177.4,66.11 U1.M35 ; v1(183.67,64.5) 184.05,64.88 U1.AF32 183.65,65.29 ; 182.49,66.03 U1.AC33 182.81,65.64 ; 181.53,73.74 U1.Y50 180.85,73.74 ; U1.AE46 183.97,72 ; U1.BJ35 195.16,66.49 ; v1(186.8,66.78) 186.82,66.78 U1.AM35 187.47,66.12 ; U1.AJ53 185.75,75.1 ; U1.D42 173.53,70.31 ; U1.D42 173.53,69.54 ; U1.D42 173.84,69.92 ; 193.8,70.23 U1.BF42 193.5,69.92 ; 194,52.03 U1.BG5 194.31,52.41 ; 187.25,71.29 U1.AN45 187.86,71.29 ; 183.59,64.88 U1.AD32 183.28,65.28 ; 194.38,52.67 U1.BG7 ; U1.BG7 194.38,53.44 ; U1.BG7 194.07,53.05 ; U1.AU53 189.36,75.1 ; U1.AN42 187.25,69.87 ; U1.AE45 183.97,71.29 ; U1.M9 177.04,53.57 ; 185.61,74.39 U1.AJ51 185.9,74.68 ; U1.U49 180.09,73.43 ; U1.AE50 183.67,74.34 ; U1.AE50 183.96,73.97 ; U1.AE50 183.3,73.97 ; 192.72,62.13 U1.BC26 192.82,61.74 ; 175.32,58.25 U1.J18 ; 180.46,57.3 U1.V16 180.14,56.91 ; 191.4,61.16 U1.BA24 191.71,61.54 ; U1.AN14 187.55,56.44 ; 178.07,51.2 U1.P4 ; U1.AV27 189.93,62.99 ; U1.AD44 183.19,71.32 ; U1.AD44 182.89,70.94 ; U1.AD44 183.19,70.56 ; v1(174.08,60.64) 174.2,60.77 U1.F24 ; 194.69,58.23 U1.BG18 194.4,57.87 ; U1.K4 176.05,51.47 ; 183.59,64.12 U1.AD30 183.28,63.73 ; U1.U14 179.78,56.44 ; U1.AT27 189.22,62.99 ; 186.01,59.93 U1.AK22 186.82,60.74 ; 194.69,68.92 U1.BG40 194.4,68.63 ; U1.BJ39 195.81,68.16 ; U1.AN48 187.25,72.72 ; U1.G14 175.22,56.28 ; 173.53,60.65 U1.D24 173.42,61.16 172.94,60.68 U1.C22 173.06,60.18 v1(173.52,60.64) 173.53,60.65
  TOP w0.178: v1(151.24,43.38) 151.63,43.78 U3.5
  TOP w0.203: 190.52,68.9 190.48,68.93 U1.AV40 189.79,68.93 ; v1(171.09,72.63) 171.49,72.23 U1.A47 ; U1.U6 U1.U5 ; U1.U6 U1.U8 ; U1.U6 180.16,52.5 ; v1(186.02,59.95) 186.4,60.33 U1.AK22 186.41,60.34 186.64,60.57 ; v1(176.04,76.69) 175.89,76.54 U1.J53 ; U1.U8 180.15,53.21 ; U1.U8 U1.U9 ; U1.U8 179.66,53.21 U1.T9 ; D2513.P 37.26,91.43 v1(37.19,91.35) ; U1.AE53 183.67,76 v1(183.53,76.14) ; R596.2 196.65,78.97 v1(196.61,78.93) ; U1.AE50 U1.AE48 U1.AE46 U1.AE45 U1.AE43 U1.AE42 U1.AE40 183.67,68.85 ; C422.1 v1(59.76,63.77) ; U1.AE11 U1.AE12 U1.AE14 183.67,56.45 ; U1.AE11 184.02,54.28 U1.AF10 ; U1.AE11 U1.AE9 U1.AE8 U1.AE6 183.67,52.19 ; U1.D16 173.25,56.99 v1(173.25,56.83) ; Q16.2 v1(100.61,15.33) ; U1.A43 171.52,70.38 v1(171.41,70.49) ; R124.1 76.75,70.56 75.6,70.56 v1(75.11,70.07) ; U1.AF27 184.06,62.61 183.79,62.34 ; U1.AN14 U1.AN12 U1.AN11 U1.AN9 U1.AN8 U1.AN6 U1.AN5 v1(187.55,51.25) ; U1.BA27 191,62.96 U1.AY28 ; U1.BA27 U1.BB27 U1.BD27 192.78,62.73 U1.BC28 ; U1.BA27 U1.AW27 U1.AV27 ; D17.P v1(48.92,18.54) ; U1.AJ25 185.95,61.85 ; U1.U14 U1.U12 U1.U11 U1.U9 ; v1(197.5,78.93) 197.68,79.11 R595.1 ; U1.AT19 U1.AV19 U1.AW19 U1.BA19 U1.BB19 U1.BD19 U1.BE19 194.18,58.72 v1(194.2,58.74) ; 189.22,62.26 U1.AT27 U1.AV27 ; U1.H27 175.27,62.49 U1.G26 ; U1.H27 175.27,62.96 ; U1.H27 U1.F27 174.25,62.61 ; U1.H27 U1.J27 U1.L27 U1.M27 U1.P27 178.42,62.61 ; U1.M14 U1.K14 176.05,56.28 ; v1(196.11,67.96) 195.93,67.96 195.48,68.41 U1.BJ39 ; CN26.1 v1(239.36,28.77) ; U1.U9 179.78,53.93 180.19,53.93 ; U1.AY34 191.35,66.38 U1.BA35 ; v1(167.39,62.67) 167.12,62.67 166.47,62.02 165.24,62.02 v1(164.78,62.48) 164.31,62.95 C13.1 ; U1.BA35 U1.BB35 U1.BD35 U1.BE35 193.79,66.49 ; U1.BA35 U1.AW35 U1.AV35 U1.AT35 188.91,66.49 ; U1.AF25 184.38,61.85 ; U1.BJ31 195.71,64.33 v1(196.11,64.33) ; U1.AG25 185.16,61.85 ; v1(171.31,58.72) U1.A19 ; U37.3 v1(11.97,91.5) ; v1(196.11,70.38) U1.BJ43 ; U1.BG1 194.44,49.93 U1.BH2 194.89,49.95 U1.BH1 ; U1.U40 U1.U42 U1.U43 U1.U45 U1.U46 U1.U48 U1.U49 ; U2523.3 32.82,92.67 v1(32.85,92.71) ; U36.3 5.9,92.89 v1(5.95,92.95) ; v1(37.83,89.83) U2524.3 ; U1.U53 v1(179.78,76.01) ; U1.W1 180.75,49.46 v1(180.99,49.21) ; U1.AV27 189.93,62.2 ; U1.AH14 U1.AH13 ; SW2.4 60.44,58.52 60.17,58.25 58.64,58.25 58.37,58.52 SW2.2 v1(57.77,57.92) ; U1.AN51 U1.AN49 U1.AN48 U1.AN46 U1.AN45 U1.AN43 U1.AN42 U1.AN40 187.55,68.73 187.47,68.65 ; U1.C20 173.42,58.72 U1.E19 U1.F19 U1.H19 U1.J19 U1.L19 U1.M19 U1.P19 ; D18.P v1(48.92,22.51) ; U1.BJ47 196,72.23 v1(196.11,72.33) ; 190.99,57.72 v1(191.41,57.72) 191.83,57.72 ; v1(182.01,75.88) 182.01,75.71 U1.AA53 ; D20.P v1(64.51,22.5) ; U1.E35 U1.F35 U1.H35 U1.J35 U1.L35 U1.M35 U1.P35 ; U1.A23 171.38,60.66 v1(171.31,60.74) ; CN26.51 237.16,16.27 v1(236.99,16.44) ; U1.AK25 186.73,61.85 ; v1(187.85,76.01) 187.55,75.72 U1.AN53 ; U1.AE1 v1(183.67,49.21) ; CN26.7 v1(237.09,27.27) ; R233.1 186.47,87.21 v1(186.5,87.18) ; CN26.33 v1(237.11,20.77) ; D2512.P v1(34.46,91.35) ; D19.P v1(64.51,18.66) ; D13.P v1(10.34,91.96) ; CN26.29 v1(237.09,21.77) ; CN26.23 v1(237.05,23.27) ; v1(196.11,66.49) U1.BJ35 ; D14.P v1(7.63,91.98)
  TOP w0.254: 167.84,66.56 167.84,67.4 167.38,67.85 163.75,67.85 163.43,67.54 163.43,64.3 v1(163.63,64.1) 163.77,63.96 C13.1 ; 167.84,66.56 v1(167.86,66.56) ; 167.84,66.56 167.84,65.72 167.36,65.24 X1.4 167.22,64.72 C12.1 ; U1.M24 176.67,61.53 v1(176.67,61.66) v1(176.04,61.66) ; U1.M24 U1.N24 177.87,61.16 178.28,61.57 178.54,61.57 ; U1.M24 U1.K24 ; v1(176.04,61.66) v1(175.4,61.66) ; v1(176.04,61.66) 176.04,61.46 U1.K24 ; 243.1,12.72 243.1,9.46 v1(242.92,9.27) ; U1.AT45 189.42,71.65 ; v1(190.64,64.58) 191,64.93 U1.AY32 190.64,65.4 v1(190.64,65.6) 190.64,65.67 U1.AY34 ; U1.AJ32 185.64,64.88 v1(186.02,65.26) ; v1(177.9,76.24) 177.84,76.17 U1.N53 ; 173.59,62.61 U1.D27 172.95,62.96 U1.C28 ; U1.BD53 192.96,75.92 v1(193.06,76.01) ; v1(171.43,64.6) 171.48,64.55 U1.A31 ; U1.C28 173.25,63.38 v1(173.25,63.57) ; U1.C28 172.95,63.09 U1.B28 ; U1.BC44 192.55,71.03 v1(192.55,71.41) ; v1(180.04,90.51) 180.22,90.69 181.2,90.69 181.62,90.26 ; v1(185.8,75.94) 185.61,75.75 U1.AJ53 ; v1(178.92,49.27) 178.81,49.38 U1.R1 ; v1(176.67,59.63) 176.67,59.83 U1.K22 U1.J22 U1.G22 ; U1.A11 v1(171.32,54.83) ; U1.K24 176.34,61.07 v1(175.91,60.64) ; 181.62,90.26 181.62,90.35 182.08,90.81 182.08,91.63 182.38,91.92 183.1,91.92 v1(183.11,91.91) 183.12,91.92 183.93,91.92 184.67,91.18 X4.2 184.67,90.63 v1(185.62,89.68) 185.62,87.83 185.26,87.47 v1(183.79,87.47) 182.97,88.29 X4.4 182.07,88.6 C155.1 181.62,88.82 181.3,88.5 181.26,88.5 v1(181.17,88.42) ; 181.62,90.26 C154.1 ; U1.L1 176.86,49.54 176.72,49.39 v1(176.72,49.3) ; C12.1 167.19,63.92 167.19,62.88 v1(167.39,62.67) ; C12.1 v1(167.83,63.95) ; U1.AN53 187.65,75.33 187.65,74.77 U1.AN51 ; U1.D24 U1.F24 174.2,61.22 v1(174.64,61.66) 174.92,61.93 U1.G26 ; U1.AP45 188.44,71.65 ; U1.A15 v1(171.18,56.78) ; v1(189.5,75.95) U1.AU53 ; U1.F1 v1(174.22,49.06) ; 25.97,40.27 26.17,40.46 v1(26.45,40.46) 26.6,40.31 27.06,40.31 27.68,39.68 27.68,38.55 25.73,36.59 23.26,36.59 22.79,36.12 20.63,36.12 20.03,36.72 17.96,36.72 17,35.76 17,23.83 10.67,17.5 v1(8.62,17.5) 5.96,17.5 5.44,18.02 5.44,20.13 5.77,20.46 v1(8.62,20.46) 11.11,20.46 15.23,24.57 15.23,36.46 17.16,38.39 20.73,38.39 21.35,37.77 22.16,37.77 22.64,38.26 24.95,38.26 26.05,39.37 26.05,39.55 25.97,39.63 25.97,40.27
  TOP w0.305: C428.2 v1(51.04,67.52) ; CN1.13 212.88,97.75 213.32,97.31 v1(213.32,97.15) ; v1(85.65,39.37) 85.86,39.17 CN9.57 ; CN1.173 212.93,47.35 v1(213.25,47.03) ; R486.1 v1(40.98,23.47) ; v1(214.01,50.35) 213.41,50.95 CN1.161 ; CN26.18 v1(229.59,24.52) ; CN1.128 v1(218.58,60.85) ; CN9.1 v1(85.69,53.17) ; CN1.167 213.22,49.15 v1(213.25,49.12) ; CN1.195 v1(213.25,40.75) ; R636.1 v1(120.86,83.11) ; v1(152.77,16.79) 152.63,16.93 R553.1 ; v1(181.62,84.92) C146.1 C147.1 R170.1 C151.1 ; CN1.72 v1(218.61,80.05) ; CN26.75 v1(239.25,10.27) ; v1(208.6,42.12) C115.1 C114.1 ; CN1.172 v1(218.58,47.65) ; CN1.61 v1(213.25,83.35) ; v1(218.55,95.51) 218.68,95.65 CN1.20 ; C458.2 v1(58.13,14.28) ; CN1.31 213.07,92.35 v1(213.38,92.65) ; v1(213.25,59.12) 213.02,59.35 CN1.133 ; CN1.3 213.03,100.75 v1(213.25,100.52) ; v1(213.25,43.75) CN1.185 210.5,43.75 R150.2 ; CN12.E1 v1(2.53,22.15) ; CN9.27 v1(85.61,46.67) ; R86.2 v1(184.44,45.18) ; v1(135.52,9.52) 135.33,9.33 C2.2 ; v1(128.89,86.2) 129.22,85.86 Q30.2 ; CN1.184 v1(218.58,44.05) ; CN26.69 v1(239.24,11.77) ; R151.2 208.6,38.52 ; Q4.2 174.01,80.99 v1(174.41,80.59) ; v1(214.01,86.35) 213.39,86.97 211.8,86.97 CN1.49 ; CN12.E2 v1(2.51,15.8) ; v1(214.01,46.15) 213.41,45.55 CN1.179 ; CN1.19 213.12,95.95 v1(213.25,95.82) ; R827.1 v1(156.97,30.77) ; U33.3 v1(51.04,63.62) ; CN9.33 v1(85.71,45.17) ; v1(217.82,99.85) 218.42,99.25 CN1.8 ; CN9.39 v1(85.66,43.67) ; CN1.65 213.41,82.15 v1(214.01,82.75) ; CN1.190 v1(218.58,42.25) ; C453.2 v1(41.92,22.47) ; CN1.127 v1(213.25,61.15) ; v1(120.76,86.97) 120.31,86.97 R755.2 ; R464.1 v1(51.63,60.38) ; v1(122.91,85.88) 123.35,85.44 Q31.2 ; CN1.25 213.41,94.15 v1(214.01,94.75) ; CN1.54 v1(218.58,85.45) ; v1(214.01,52.14) 213.4,52.75 CN1.155 ; CN1.32 v1(218.58,92.05) ; R681.1 119.28,81.11 v1(119.96,81.11) ; CN9.3 v1(85.71,52.67) ; CN1.48 v1(218.58,87.25) ; CN1.134 v1(218.58,59.05) ; R756.1 120.62,85.12 120.88,84.85 v1(120.88,84.82) ; CN9.75 v1(87.97,34.67) ; CN1.178 v1(218.58,45.85) ; v1(236.77,19.16) 236.88,19.27 CN26.39 ; CN1.44 v1(218.58,88.45) ; v1(90.05,36.78) R564.2 ; CN1.43 212.96,88.75 v1(213.25,88.46) ; CN9.73 v1(87.97,35.17) ; CN1.71 v1(213.25,80.35) ; U9.15 v1(172.85,94.63) ; CN1.37 v1(213.25,90.55) ; CN1.156 v1(218.58,52.45) ; R491.1 v1(60.6,18.67) ; CN26.45 v1(236.84,17.77) ; CN26.36 v1(229.58,20.02) ; CN26.57 v1(237.04,14.77) ; v1(182.2,93.93) 182.18,93.95 R176.1 181.66,94.75 C153.1 ; CN1.145 v1(213.25,55.75) ; CN1.139 v1(213.25,57.55) ; CN1.168 v1(218.58,48.85) ; CN1.14 v1(218.58,97.45) ; CN9.9 v1(85.71,51.17) ; CN1.196 218.42,40.45 v1(217.82,41.05) ; CN1.151 v1(213.25,53.95) ; v1(214.01,99.55) 214.01,99.44 213.52,98.95 CN1.9 ; CN1.38 v1(218.58,90.25) ; CN1.189 v1(213.25,42.55) ; CN1.26 v1(218.58,93.85) ; CN9.51 v1(85.65,40.67) ; CN1.55 v1(213.25,85.15) ; CN9.21 v1(85.78,48.17) ; CN1.66 v1(218.58,81.85) ; CN1.144 v1(218.58,56.05) ; v1(218.58,101.28) 218.82,101.05 CN1.2 ; CN26.63 237.34,13.27 236.86,13.75 v1(236.86,13.87) ; v1(218.58,57.85) CN1.138 ; CN1.162 v1(218.58,50.65) ; CN26.24 v1(229.58,23.02) ; CN1.150 v1(218.58,54.25) ; CN9.45 v1(85.7,42.17) ; R178.2 v1(168.1,93.45) ; CN9.71 v1(87.99,35.67) ; CN1.60 v1(218.58,83.65) ; R19.1 v1(174.95,84.14) ; CN9.15 v1(85.76,49.67)
  TOP w0.381: v1(171.42,23.29) 171.42,23.29 C210.2 ; R75.2 v1(180.74,83.07) ; C10.1 C8.1 152.89,41.61 v1(153.14,41.35) ; R77.1 182.77,83.43 v1(182.87,83.53) ; v1(150.31,48.48) 150.39,48.56 C11.1 ; v1(153.37,49.25) 153.4,49.22 C9.1 ; C427.2 45.31,81 v1(45.31,81.25) ; R78.1 R56.2 ; R74.2 v1(183.79,83.63) ; R170.1 182.26,87.06 v1(182.39,87.19) ; R76.2 v1(181.83,83.58) ; R59.2 v1(185.95,83.63) ; v1(199.6,98.1) R585.1
  TOP w0.406: v1(108.75,34.61) 108.74,34.6 C350.1 ; C358.1 v1(109.41,37.79) ; C105.2 172.86,47.66 v1(172.86,47.66) ; v1(159.79,13.18) 159.66,13.18 C822.2 ; C144.2 178.1,27.96 v1(177.93,27.79) ; C426.1 v1(50.33,66.91) ; v1(77.16,88.84) 76.6,88.84 76.3,88.55 CN23.6 ; v1(159.58,96.75) 159.57,96.76 C306.1 C305.1 v1(159.66,95.94) ; v1(180.13,91.25) C152.1 C148.1 ; CN23.3 v1(68.8,89.59) ; v1(159.79,12.65) 159.84,12.6 159.84,11.43 159.69,11.28 159.69,11.27 C691.2 ; R56.2 v1(176.8,80.71)
  TOP w0.508: v1(245.48,19.79) CN10.E2 ; J4.7 v1(8.95,92.98) ; v1(99.49,71.43) 99.73,71.2 CN3.S7 ; v1(139.46,15.48) 139.46,15.47 CN25.E2 ; v1(103.26,78.51) 102.95,78.82 CN3.S1 ; U4.E1 160.38,42.49 U4.4 U2.4 ; CN9.E2 v1(87.93,33.53) ; CN18.4 v1(32.85,92.71) ; v1(182.27,95.15) 182.91,95.15 C149.1 ; v1(99.56,51.11) 99.8,50.88 CN3.P12 ; v1(208.38,96.57) 208.71,96.9 C116.1 ; CN1.E1 v1(230.94,36.9) ; CN1.E2 v1(230.95,102.5) ; v1(109.5,96.16) R3100.1 R495.1 v1(109.5,92.42) R663.1 v1(109.5,90.58) R707.1 ; v1(99.49,75.24) 99.73,75.01 CN3.S4 ; CN3.P6 100.13,58.5 99.16,59.46 v2(99.16,60) 99.88,60 100.11,59.77 CN3.P5 ; Q1.2 131.13,10.75 130.62,11.26 C1.1 130.62,12.41 v1(131.81,13.6) ; J4.4 v1(5.95,92.95) ; CN9.E1 v1(84.4,54.31) ; U39.2 v1(41.99,20.36) ; CN23.E2 v1(58.85,90.93) ; CN23.E3 v1(83.43,103.9) ; v1(136.33,14.28) 135.58,15.02 C565.1 ; R152.1 C116.1 ; C116.1 C117.1 ; v1(165.62,67.23) 165.34,66.94 X1.2 ; CN18.7 35.85,92.87 v1(35.86,92.87) ; U34.4 v1(50.82,73.83) ; CN25.4 v1(135.79,10.15) ; CN10.E1 v1(243.82,11.92) ; v1(99.43,61.27) 99.67,61.04 CN3.P4 ; CN26.E2 238.9,9.13 v1(239.5,9.73) ; v1(99.55,53.65) 99.79,53.42 CN3.P10 ; CN26.E1 v1(239.43,29.91) ; U40.2 v1(60.23,14.89) ; CN23.E1 v1(84.65,90.87) ; C150.1 v1(182.74,94.14) ; CN25.E1 v1(139.46,9.77) ; v1(55.21,104.17) 55.48,103.9 CN23.E4
  LAY4 w0.203: v1(25.53,42.99) 25.53,42.65 24.21,41.32 24.21,39.84 25.03,39.02 25.77,39.02 26.01,39.26 26.01,40.02 v1(26.45,40.46) 26.72,40.73 27.88,40.73 28.59,41.44 v1(29.04,41.44) 29.43,41.84 36.03,41.84 44.95,32.92 44.95,13.77 47.35,11.37 56.61,11.37 60.3,7.69 89.98,7.69 92.63,10.33 95.02,10.33 97.66,7.69 113.19,7.69 116.66,11.15 127.4,11.15 130.86,7.69 145.23,7.69 147.93,10.39 150.13,10.39 152.83,7.69 229.25,7.69 232.76,11.19 235.26,11.19 238.67,7.78 242.13,7.78 242.92,8.56 v1(242.92,9.27)
  LAY4 w0.254: v1(239.5,9.73) 238.91,9.73 235.9,12.74 232.12,12.74 228.78,9.4 153.47,9.4 150.92,11.96 147.02,11.96 144.47,9.4 131.34,9.4 128,12.74 115.89,12.74 112.56,9.4 98.27,9.4 95.65,12.03 92.1,12.03 89.48,9.4 61.89,9.4 58.22,13.08 47.99,13.08 46.58,14.48 46.58,33.93 37.06,43.46 26,43.46 v1(25.53,42.99)
  BOTTOM w0.076: 184.98,31.55 184.98,30.88 U8.Y2 184.46,30.88 184.46,31.55
  BOTTOM w0.102: 27.6,47 27.6,47
  BOTTOM w0.178: v1(27.02,35.56) 27.31,35.84 U25.4 ; v1(61.78,70.74) 61.78,70.73 U31.1 ; v1(60.73,60) 60.87,59.86 U31.27 ; U31.91 v1(47.65,68.26) ; v1(77.45,66.14) 77.46,66.15 U30.6 ; v1(48.31,61.7) 48.15,61.86 U31.75 ; v1(53.93,55.1) U31.49 ; U32.6 77.46,62.03 v1(77.46,62.03) ; v1(123.55,41.5) U22.24
  BOTTOM w0.203: v1(183.67,49.21) 184.04,48.85 C7.2 ; U8.Y5 U8.AA6 185.35,28.62 185.72,28.25 v1(185.72,28.05) ; U6.6 77.46,57.14 77.3,56.98 v1(76.85,56.98) ; C706.1 v1(70.26,97.08) ; U8.K4 180.2,29.14 v1(180.2,29.06) ; v1(33.77,26.47) 33.6,26.65 R341.1 ; v1(182.88,59.2) 183.05,59.2 183.63,58.61 C26.1 ; U5.4 114.71,45.93 v1(115,46.23) ; v1(180.79,73.95) 180.79,73.95 R567.1 ; C823.1 R842.2 146.74,14.94 v1(146.73,14.95) ; v1(186.44,29.62) 186.43,29.62 U8.AA4 ; v1(154.41,93.44) 154.31,93.35 U16.17 ; U16.3 v1(156.64,97.97) ; R597.1 183.09,36.52 v1(183.02,36.59) ; C390.1 v1(35.56,30.29) ; R594.1 v1(171.06,75.46) ; R593.2 198.4,47.57 v1(198.14,47.83) ; R258.2 v1(64.89,56.45) ; U8.M7 181.02,28.12 v1(181.72,27.42) 181.72,27.12 U8.R10 ; v1(149.69,92.18) 149.91,92.4 U16.28 ; v1(181.98,28.63) 181.98,28.74 181.72,29 U8.P5 ; U16.18 153.91,93.29 v1(153.8,93.4) ; CN11.3 v1(52.96,43.59) ; U8.U8 183.6,27.62 v1(183.61,27.63) ; R443.2 53.6,54.77 v1(53.93,55.1) ; C268.1 166.99,38.01 167.2,38.21 168.68,38.21 ; R448.2 v1(66.76,60.11) ; Q40.2 v1(221.78,21.87)
  BOTTOM w0.254: v1(118.64,32.25) 118.64,31.86 119.28,31.23 v1(119.28,29.97) 119.28,29.24 119.53,28.99 X5.2 120.34,28.43 120.71,28.06 123.34,28.06 123.85,28.57 v1(123.85,30.09) 123.85,30.32 123.61,30.56 123.6,30.56 123.47,30.69 X5.4 122.46,30.77 122.36,30.77 120.88,32.25 v1(120.68,32.25) ; CN11.19 44.96,43.62 v1(44.88,43.7) ; v1(112.55,78.49) 112.56,78.5 R224.1 ; v1(180.74,72.07) 180.74,72.42 R16.2 ; v1(178.5,60.65) 178.13,61.02 178.13,61.92 ; C56.1 C68.1 ; C47.1 184.33,65.79 C60.1 ; U42.3 v1(145.59,85.11) ; CN11.17 45.96,43.62 v1(46.09,43.75) 46.46,43.38 CN11.16 ; R458.1 61.27,76.16 61.88,76.77 66.4,76.77 67.59,75.58 v1(68.28,75.58) 68.28,75.58 v1(71.53,75.58) X6.2 X6.3 v1(71.53,74.38) 67.5,74.38 v1(67.21,74.09) 66.92,73.8 63.34,73.8 62.76,73.22 v1(62.76,71.3) ; 160.31,47.45 X2.3 X2.2 163.06,46.64 v1(163.37,46.96) 163.45,47.04 v1(163.45,52.05) 163.44,52.06 C16.1 164.43,53.24 165.26,54.07 165.26,55.14 164.31,56.09 v1(164.01,56.09) C20.1 163.11,56.09 162.91,56.29 v1(161.64,56.29) 161.63,56.27 161.08,56.27 160.31,55.5 160.31,47.45
  BOTTOM w0.305: C702.1 78.38,93.89 v1(79.05,93.89) 79.05,93.01 C703.2 ; C704.2 v1(76.26,100.77) ; C58.1 173.15,54.71 v1(173.25,54.8) ; v1(154.95,73.03) 154.03,73.03 153.49,72.5 C256.1 ; R232.1 180.92,71.89 v1(180.74,72.07) ; U41.3 123.85,86.85 v1(123.7,87) ; C179.2 110.76,65.1 110.58,64.92 C181.2 v1(110.28,64.37) ; R481.1 v1(48.73,94.32) ; R538.2 96.02,90.39 v1(96,90.38) ; R3113.1 166.66,73.39 167.23,73.97 v1(167.23,74.01) ; R145.1 175.93,98.8 v1(175.95,98.8) ; v1(171.36,51.28) 171.75,51.67 R135.2 ; R474.1 20.13,86.48 v1(20.25,86.6) 20.49,86.36 C441.2 ; v1(134.36,88.92) 134.36,88.6 134.36,88.6 R255.2 ; v1(156.58,65.56) 156.65,65.56 Q20.2 ; C286.1 139.7,88.25 v2(140.27,87.68) ; v1(182.77,70.55) 183.31,70.01 C83.1 ; C710.1 v1(75.26,99.83) ; Q51.2 147.45,81.47 v1(148.15,80.77) 148.14,80.75 R544.2 ; C109.1 C71.1 176.63,59.04 C72.1 175.66,58.36 175.28,57.98 v1(175.28,57.72) ; R267.1 R266.1 148.37,90.23 v1(148.37,90.23) ; U27.3 228.93,19.31 v1(229.16,19.08) ; C295.1 v1(152.72,102.61) ; Q23.2 111.63,78.04 v1(111.19,78.48) ; C701.2 79.2,96.75 C708.2 C700.2 v1(79.99,98.57) ; Q8.2 v1(166.22,60.56) ; R599.2 173.7,35.96 173.4,35.65 v1(173.4,34.57) ; C448.2 v1(47.69,93.65) ; v1(36.06,32.97) 35.84,33.19 Q37.2 36.65,33.61 37.64,34.6 U26.3 ; R3106.2 v1(156.73,51.35) ; R453.1 v1(44.25,57.54) ; R91.2 R92.2 168.8,73.96 v1(169.14,74.3) ; C364.2 18.83,36.7 v1(18.92,36.62) ; v1(160.12,69.06) 160.01,68.95 R218.1 159.02,68.88 Q19.2 ; U44.2 v1(167.32,31.92) ; v1(78.54,72.45) 78.54,72.46 U29.2 ; R275.1 v1(152.14,89.65) ; C727.1 v1(117.7,88.52) ; C304.1 v1(146.71,96.57) ; C705.2 v1(70.88,99.23) ; v1(118.42,57.6) 118.42,57.47 R184.2 ; Q50.2 v1(148.63,86.7) ; C368.1 19.24,38.11 C367.1 18.25,39.1 v1(17.82,39.1) ; R800.2 v1(72.32,99.79) ; C301.1 v1(159.44,92.85) ; v1(73.16,97.68) C707.2 R802.1 ; C307.1 v1(159.58,96.75) ; v1(175.91,54.8) 176.01,54.71 C45.1 ; v1(113.07,44.19) 112.69,44.19 C15.2 ; Q5.2 v1(176.11,94.48) ; R2984.1 v1(182.01,75.88) ; v1(177.44,65.6) 177.94,65.09 C68.1 ; R958.1 v1(122.96,82.57) ; C113.2 v1(176.54,98.67) ; Q48.2 v1(102.31,94.03) ; C14.2 v1(112.43,47.54) ; R131.1 177.42,71.02 R132.1 ; Q39.2 v1(226.27,23.28) ; R531.2 v1(119.85,88.71) ; Q38.2 v1(41.7,34.4)
  BOTTOM w0.381: R313.2 119.27,44.68 v1(119.27,44.68) ; C419.2 75.32,69.86 v1(75.11,70.07) ; v1(198.14,47.83) C91.2 ; v1(180.74,72.07) 180.58,71.91 R130.1 ; v1(60.6,76) R458.1 ; C89.1 178.1,67.47 v1(178.07,67.5) ; C86.1 v1(175.28,69.41) ; v1(193.31,62.55) 192.93,62.93 R1.2 ; v1(176.04,67.5) 176.07,67.47 R100.1 ; R82.2 168.52,60.46 v1(168.52,60.46) ; v1(74.32,64.34) C421.2 ; v1(188.36,66.74) 188.71,66.39 C70.1 ; C389.1 v1(31.31,35.11) 31.31,35.87 C392.1 ; C21.2 v1(79.46,61.04) ; v1(80.63,68.39) 80.47,68.55 C418.2 ; C47.1 183.75,64.59 v1(183.67,64.5) ; C110.1 182.04,66.72 v1(182.1,66.78) ; C108.1 182.39,55.69 182.77,55.31 v1(182.77,55.23) ; 160.57,25.3 161.33,26.06 C218.2 ; R380.1 v1(216.66,12.25) ; C417.2 43.01,60.77 42.62,60.38 v1(42.62,59.87) ; v1(121.56,32.25) C331.2 ; R300.1 v1(127.53,38.09) ; C22.2 v1(74.32,60.89) ; C64.1 187.68,63.68 v1(187.59,63.77) 187.59,64.08 187.19,64.48 C44.1 ; v1(181.31,59.2) 181.37,59.25 C46.1 181.37,60.55 C84.1 C78.1 ; C336.2 v1(127.53,35.94) ; v1(186.02,59.95) 186.72,60.66 C34.2 ; v1(122.45,32.25) C345.2 C329.2 ; R132.1 177.09,71.35 177.09,71.77 v1(176.88,71.98) ; v1(185.95,83.63) 185.95,83.51 R57.2 ; R80.1 173.86,53 v1(173.86,52.14) ; v1(183.68,80.36) R49.1 ; v1(183.67,67.54) 183.51,67.38 C57.1 ; C101.1 173.01,51.48 v1(173.02,51.49) ; C107.1 C103.1 180.66,55.98 v1(180.74,56.06) ; C65.1 184.22,61.28 v1(183.66,60.72) ; C63.1 186.67,72.04 v1(186.58,71.95) 186.33,71.69 C67.1 ; C62.1 v1(185.18,56.94) 185.08,56.83 C28.1 183.75,57.34 C25.1 C26.1 ; v1(60.6,75.36) 60.6,75.35 60.84,75.11 C423.2 ; C82.1 190.61,65.63 v1(190.64,65.6) ; C343.2 v1(127.53,38.98) ; C53.1 C97.1 181.37,56.45 v1(181.75,56.07) ; v1(179.75,63.75) 180.36,63.13 C96.1 ; v1(58.32,77.36) R463.2 ; C425.2 v1(61.27,73.32) ; v1(182.1,63.75) 182.25,63.59 C27.1 182.26,63 C85.1 ; C366.2 17.8,32.13 v1(17.8,32.52) ; C79.1 C95.1 ; C79.1 180.68,69.81 180.61,69.81 C81.1 ; C79.1 181.25,69.41 v1(181.75,69.92) ; C414.2 v1(74.92,73.78) ; C112.2 185.66,49.31 v1(185.66,49.21) ; C341.2 v1(118.64,32.25) ; v1(116.29,28.6) 116.29,28.6 C325.2 ; v1(180.48,68.32) 180.48,68.51 C90.1 ; v1(176.72,49.3) 176.72,49.59 R20.2 ; v1(195.16,47.38) 195.61,47.83 C80.2 ; v1(186.05,56.91) 186.05,56.94 186.07,56.96 C66.1 ; v1(113.25,41.48) 113.48,41.7 C328.2 ; v1(178.92,49.27) 179.09,49.43 R93.1 ; C342.2 116.83,44.2 116.4,44.2 v1(116.4,44.2) ; v1(74.01,56.57) 74.01,56.9 C24.1 ; C362.1 25.52,43 v1(25.53,42.99) ; C23.1 v1(73.67,58.23) ; v1(213.82,12.79) C412.1 ; C382.1 24.07,40.55 24.07,40.99 v1(23.73,41.34) ; v1(31.62,38.43) 31.62,38.43 C386.2 31.78,37.48 C395.1 ; R21.2 176.43,50.61 v1(175.91,51.12) ; C388.1 29.55,31.8 v1(29.14,32.2) ; R84.2 171.42,58.61 v1(171.31,58.72) ; C424.2 v1(65.56,66.98) ; R230.1 186.94,85.62 v1(186.78,85.46) ; v1(191.53,53.15) 191.9,53.52 C92.2 192.55,53.91 v1(192.68,53.79) ; C43.1 189.88,59.76 v1(190.01,59.63) 190.01,59.25 189.63,58.87 C42.1 ; v1(120.68,32.25) C324.2 ; R129.2 179.85,64.4 v1(179.75,64.5) ; v1(188.49,56.07) 188.23,56.33 C88.1 ; C420.2 v1(81.14,65.47) ; C566.1 76.86,56.1 77.34,55.62 v1(77.34,55.42) ; C327.2 v1(127.53,40) ; C111.1 187.16,56.74 v1(187.59,56.74) ; C48.1 v1(190.01,60.64) ; C106.1 179.81,65.2 v1(179.75,65.26) ; C391.1 v1(34.05,33.92) ; R47.1 C102.1 C104.1 168.26,63.95 v1(167.83,63.95) ; v1(30.75,34.08) C385.1 ; C59.1 187.65,68.26 v1(187.77,68.39) 187.77,69.14 C61.1 ; R298.1 v1(127.53,37.21) ; R462.2 v1(53.87,75.74) ; R307.2 v1(127.53,41.78) ; C143.2 v1(182.09,36.6) ; C323.2 v1(119.66,32.25) ; R452.2 v1(48.16,75.74)
  BOTTOM w0.406: v1(127.48,83.26) R638.1 R754.2 ; C237.2 162.79,18.91 v1(162.05,19.65) ; v1(115.09,85.96) 115.5,85.55 C992.2 ; C19.2 169.07,59.91 R82.2 ; Q49.2 98.07,94.04 v1(98.12,94.09) ; R648.2 v1(127.49,82) ; v1(180.67,97.37) 180.67,97.37 U7.3 ; v1(159.79,94.64) 159.79,94.29 C300.1 ; CN11.E2 42.77,42.74 v1(42.96,42.92) ; v1(168.68,21.45) 169.21,20.93 C215.2 ; C98.1 171.45,53.06 v1(171.25,52.86) ; R60.1 v1(183.53,76.14) ; v1(168.77,54.28) 168.8,54.32 R121.1 C17.1 168.9,55.11 168.57,55.44 C18.2 ; v1(163.6,19.58) 163.84,19.83 C238.2 ; C413.2 v1(77.85,74.24)
  BOTTOM w0.508: v1(123.54,44.74) 123.31,44.51 C348.1 C349.2 ; J5.E1 113.94,91.07 v1(113.37,91.07) ; v1(144.66,45.01) 144.35,45.33 U46.2 ; v1(55.65,42.86) CN11.E1 ; Q45.2 133.84,22.94 v1(133.83,22.95) ; R303.2 v1(129.31,39.36) ; v1(108.45,65.39) 108.45,65.09 108.27,64.91 C180.2 ; C374.2 v1(33.15,43.93) ; U38.2 v1(48.71,89.56) ; v1(154.69,91.65) 154.96,91.38 C310.1 C311.1 ; CN35.31 v1(132.91,102.89) ; C40.2 196.59,41.9 197.1,41.39 v2(197.1,40.46) ; C335.1 v1(129.31,33.4) ; C359.1 v1(109.36,39.05) ; C309.2 v1(154.06,89.28) ; CN35.7 v1(135.91,94.69) ; v1(138,97.2) 138.53,97.2 138.91,96.82 CN35.4 ; CN24.2 v1(9.4,68.6) ; C416.1 v1(41.48,59.56) ; C423.2 R458.1 ; R838.2 v2(197.32,19.32) ; Q42.2 v1(69.18,70.34) ; Q22.2 v1(109.15,74.09) 108.76,73.71 C260.1 ; v1(115.67,26.99) R301.1 ; v1(153.96,55.53) 153.67,55.24 C436.2 ; C175.1 122.1,66.77 v2(122.1,67.1) ; J5.E2 v1(108.02,90.45) ; C176.1 v1(120.43,67.17) ; CN35.E2 v1(122.02,97.55) ; C360.2 19.26,26 v1(19.26,26.62) ; U21.2 112.89,29.1 v1(112.88,29.11) ; R601.2 v1(116.06,58.85) ; R181.2 120.44,57.42 v1(120.01,56.99) ; CN35.37 138.91,102.65 v1(139.27,103.01) ; CN35.40 v1(141.91,103.07) ; v1(124.73,30.1) 124.76,30.14 125.68,30.14 C337.1 ; v1(130.01,26.57) 130.01,26.57 R501.1 ; CN35.19 v1(123.91,97.22) ; C411.2 v1(213.7,16.22) ; C351.1 108.73,34.62 v1(108.75,34.61) ; v1(134.68,86.14) 134.68,86.15 U15.2 ; C405.2 v1(225.44,18.71) ; CN35.21 v1(122.91,103.07) ; CN35.12 v1(130.91,94.78) ; C334.1 v1(112.29,26.21) ; R297.2 v1(118.21,29.24) ; Q46.2 v1(132.38,24.93) ; v1(120.9,56.95) C156.2 v1(122.37,56.95) 122.37,56.99 122.75,57.36 R179.2 ; C446.2 v2(41.31,92.02) ; C308.2 v1(160.04,91.71) ; CN35.20 v1(122.91,97.25) ; CN35.E1 143.91,98.59 v1(144.36,99.03) ; C214.2 158.62,20.27 v1(158.62,19.65) ; U35.2 v1(15.85,84.89) ; Q43.2 v1(69.18,63.98) ; U28.2 v1(218.39,14.31) ; CN35.28 v1(129.91,102.98) ; R600.2 v1(117.05,58.87) ; CN35.25 v1(126.91,102.94) ; CN35.22 v1(123.91,103.02) ; C488.1 v1(39.21,75.22) ; R182.1 v1(125.03,58.39) ; CN35.1 v1(141.91,94.82) ; CN35.34 v1(135.91,102.91)
  vias: v1(1.23,45.12) v1(1.36,42.6) v1(3.27,46.42) v1(3.25,41.49) v1(4.82,88) v1(5.34,45.1) v1(5.37,42.58) v1(6.9,87.97) v1(7.94,87.31) v1(9.98,87.3) v1(11.95,85) v1(19.51,82.44) v1(19.66,45.98) v1(20.32,101.63) v1(20.3,44.8) v1(20.31,44.17) v1(21.27,103.39) v1(21.26,99.9) v1(21.69,8.94) v1(22.16,45) v1(22.42,7.43) v1(23.13,11.25) v1(23.3,36.49) v1(23.3,34.72) v1(23.3,33.19) v1(23.4,103.39) v1(23.4,99.91) v1(23.99,41.88) v1(24.55,101.62) v1(24.83,34.84) v1(24.85,33.3) v1(24.95,36.49) v1(25.12,11.18) v1(26.13,7.6) v1(26.21,33.33) v1(26.35,36.49) v1(26.33,34.98) v1(26.49,9.63) v1(27.64,92.57) v1(28.49,36.26) v1(28.77,38.62) v1(29.02,40.51) v1(29.6,88.95) v1(29.62,39.62) v1(31.41,88.49) v1(32.14,78.26) v1(32.27,40.86) v1(32.46,35.12) v1(32.8,38.06) v1(33.75,31.37) v1(34.62,88.25) v1(35.86,92.28) v1(36.1,34.46) v1(36.91,88.3) v1(37.32,89.8) v1(37.97,38.61) v1(38.08,33.94) v1(40.01,32.42) v1(40.44,12.09) v1(40.5,73.52) v1(41.31,25.46) v1(41.39,13.86) v1(41.38,10.36) v1(41.82,38.72) v1(42.48,54.91) v1(43.43,72.69) v1(43.52,13.86) v1(43.52,10.37) v1(44.3,91.92) v1(44.31,76.73) v1(44.61,73.91) v1(44.67,12.09) v1(44.8,64.32) v1(45.07,91.94) v1(45.25,78.93) v1(47.22,14.64) v1(48.05,54.57) v1(48.94,15.08) v1(49.04,29.82) v1(49.22,81.23) v1(49.46,68.89) v1(49.37,44.45) v1(49.73,81.75) v1(50,52.36) v1(51,57.59) v1(51.02,29.82) v1(51.99,75.88) v1(53.43,68.33) v1(53.51,65.93) v1(53.86,43.97) v1(55.12,67.44) v1(55.7,52.8) v1(56.59,83.74) v1(56.98,80.07) v1(57.11,85.44) v1(57.27,60.05) v1(57.27,30.35) v1(58.66,85.16) v1(58.69,63.71) v1(58.86,31.99) v1(59.27,30.34) v1(59.63,54.03) v1(59.84,70.01) v1(59.79,68.94) v1(59.89,55.32) v1(60.12,84.26) v1(60.14,82.01) v1(61.38,52.41) v1(62.26,55.99) v1(63.54,52.93) v1(65.78,92.46) v1(66.48,66.48) v1(67.92,64.99) v1(68.43,91.83) v1(69,66.85) v1(70.09,42.19) v1(70.46,61.9) v1(70.39,59.2) v1(72.09,89.92) v1(72.91,72.04) v1(73.26,95.39) v1(73.26,94.62) v1(73.26,93.86) v1(73.23,66.5) v1(73.34,32.59) v1(73.71,42.14) v1(74.02,95.39) v1(74.02,94.62) v1(74.02,93.86) v1(74.34,75.47) v1(74.78,95.39) v1(74.78,94.62) v1(74.78,93.86) v1(74.98,70.97) v1(75.04,29.58) v1(75.49,91.77) v1(75.62,35.29) v1(75.71,12.47) v1(75.82,53.05) v1(75.99,31.34) v1(75.99,27.85) v1(76.38,56.98) v1(76.51,65.32) v1(77.18,75.53) v1(77.41,44.62) v1(78.12,31.34) v1(78.13,27.86) v1(78.19,95.67) v1(78.19,94.59) v1(78.25,12.24) v1(79.27,29.57) v1(79.37,66.2) v1(80.38,91.61) v1(81.44,64.25) v1(82.5,55.73) v1(82.71,35.44) v1(83.61,60.96) v1(84.36,75.24) v1(84.59,96.77) v1(84.62,94.68) v1(84.61,60.97) v1(85.3,56.27) v1(86.2,75.54) v1(87.33,93.43) v1(88.98,90.01) v1(92.04,44.76) v1(92.85,46.36) v1(93.62,47.99) v1(99.57,18.65) v1(99.57,15.9) v1(102.37,102.6) v1(102.52,10.67) v1(103.31,104.36) v1(103.31,100.86) v1(103.61,38.9) v1(103.61,36.16) v1(103.88,14.09) v1(104.83,15.85) v1(104.82,12.36) v1(105.44,104.36) v1(105.45,100.88) v1(106.59,102.59) v1(106.62,55.49) v1(106.7,77.48) v1(106.75,53.85) v1(106.95,15.85) v1(106.96,12.37) v1(107.26,81.32) v1(107.99,56.02) v1(108.1,14.08) v1(108.4,41.88) v1(108.49,22.75) v1(109.09,40.38) v1(109.1,21.6) v1(109.71,36.75) v1(109.92,34.1) v1(110.89,66.71) v1(112.92,49.19) v1(113.04,40.13) v1(113.06,38.88) v1(113.14,32.27) v1(113.24,37.63) v1(113.37,37.1) v1(113.73,35.35) v1(113.83,24.35) v1(113.95,22.73) v1(114.12,34.24) v1(114.69,34.21) v1(115.6,40.13) v1(115.65,37.56) v1(115.67,38.86) v1(117.48,7.3) v1(118.58,63.94) v1(119.15,40.38) v1(119.15,38.6) v1(119.15,36.82) v1(119.29,45.51) v1(120.56,62.4) v1(120.56,61.13) v1(120.7,18.2) v1(120.88,85.88) v1(120.93,40.38) v1(120.93,38.6) v1(120.93,36.82) v1(121.83,62.4) v1(121.83,61.13) v1(121.9,86.96) v1(121.89,85.88) v1(121.9,84.82) v1(122.71,40.38) v1(122.71,38.6) v1(122.71,36.82) v1(122.92,86.96) v1(122.92,84.82) v1(123.85,61.27) v1(124.31,60.77) v1(124.38,61.25) v1(124.42,10.58) v1(125.42,47.03) v1(126.87,7.3) v1(127.69,49.36) v1(128.84,88.9) v1(128.88,86.69) v1(128.93,48.32) v1(129.15,47.71) v1(129.24,84.84) v1(129.35,88.91) v1(129.77,84.84) v1(130.23,45.59) v1(130.93,47.8) v1(131.62,41.23) v1(132.34,17.11) v1(132.48,40.28) v1(132.77,46.25) v1(132.9,94.38) v1(133.44,94.38) v1(133.68,103.52) v1(133.97,39.42) v1(136.4,100.6) v1(138.36,100.55) v1(139.41,100.57) v1(140.72,42.6) v1(141.4,100.55) v1(145.48,47.38) v1(145.93,47.38) v1(149.17,67.25) v1(149.5,63.31) v1(149.87,55.47) v1(150.38,67.64) v1(150.42,55.46) v1(150.52,103.57) v1(151.27,97.45) v1(151.27,96.18) v1(151.27,94.91) v1(151.87,45.16) v1(152.23,52.66) v1(152.43,30.74) v1(152.54,97.45) v1(152.54,96.18) v1(152.54,94.91) v1(152.53,63.74) v1(152.58,103.41) v1(152.58,53.01) v1(152.66,13.8) v1(152.67,13.33) v1(152.76,11.8) v1(152.8,68.57) v1(152.91,53.34) v1(152.89,45.16) v1(153.01,23.17) v1(153.09,65.39) v1(153.27,16.79) v1(153.33,23.57) v1(153.48,23.13) v1(153.81,97.45) v1(153.81,96.18) v1(153.81,94.91) v1(154.31,102.63) v1(155.08,55.56) v1(155.46,102.57) v1(155.65,55.56) v1(155.84,78.09) v1(156.1,39.53) v1(156.46,84.29) v1(156.7,45.67) v1(156.69,43.27) v1(157.15,84.32) v1(157.09,39.32) v1(157.26,14.12) v1(157.25,13.51) v1(157.25,13) v1(157.25,12.52) v1(157.25,12.01) v1(157.48,16.98) v1(157.86,39.32) v1(158.1,44.4) v1(158.65,24.73) v1(158.62,23.08) v1(158.62,21.3) v1(159.12,43.31) v1(159.8,13.68) v1(159.87,45.74) v1(160.14,69.58) v1(160.13,68.54) v1(160.12,68.05) v1(160.4,24.73) v1(160.4,23.08) v1(160.4,21.3) v1(160.4,19.65) v1(161.13,73.6) v1(161.31,80.4) v1(161.3,75.28) v1(161.38,70.62) v1(161.59,90.06) v1(161.64,73.6) v1(161.76,64.66) v1(161.79,40.6) v1(162.05,24.73) v1(162.05,23.08) v1(162.05,21.3) v1(162.41,66.21) v1(162.81,91.37) v1(162.91,74.68) v1(163.09,79.82) v1(163.35,70.64) v1(163.58,24.73) v1(163.58,22.78) v1(163.58,21.3) v1(163.98,98.73) v1(164.07,70.56) v1(164.04,61.99) v1(164.1,92.48) v1(164.21,90.92) v1(164.63,82.44) v1(164.72,48.31) v1(164.8,70.56) v1(164.96,59.5) v1(165.05,60.81) v1(165.35,80.18) v1(165.51,70.54) v1(165.62,92.84) v1(165.91,44.32) v1(166,98.73) v1(166.06,48.51) v1(166.03,47.99) v1(166.03,47.47) v1(166.01,45.44) v1(166.13,84.16) v1(166.09,74.49) v1(166.35,52.47) v1(166.43,55.08) v1(166.67,75.94) v1(167.53,74.51) v1(167.54,52.03) v1(167.64,77.42) v1(167.76,28.76) v1(168.04,98.65) v1(168.13,84.1) v1(168.26,28.78) v1(168.93,80.39) v1(169.24,38.16) v1(169.29,82.75) v1(169.27,76.9) v1(170.08,28.77) v1(170.64,74.21) v1(170.65,46.57) v1(170.59,28.79) v1(171.44,47.05) v1(171.66,50.07) v1(171.74,66.98) v1(171.98,79.76) v1(172.27,78.93) v1(172.28,77.81) v1(172.88,72.73) v1(172.99,73.73) v1(173.12,70.42) v1(173.25,69.4) v1(173.25,68.39) v1(173.25,67.5) v1(173.37,71.69) v1(173.4,15.34) v1(173.61,74.25) v1(173.77,18.26) v1(173.83,31.71) v1(173.88,80.18) v1(173.88,70.55) v1(173.88,69.41) v1(174.01,71.44) v1(174.23,77.85) v1(174.36,86.01) v1(174.33,40.92) v1(174.52,70.42) v1(174.52,69.41) v1(174.52,55.82) v1(174.64,71.44) v1(174.64,65.6) v1(174.74,13.7) v1(174.78,27.46) v1(174.89,29.14) v1(174.96,11.37) v1(175.28,63.57) v1(175.31,28.09) v1(175.38,68.39) v1(175.4,55.82) v1(175.56,39.8) v1(175.49,14.45) v1(175.51,11.37) v1(175.63,29) v1(175.89,74.02) v1(175.91,73.32) v1(175.91,53.15) v1(175.98,78.68) v1(176.04,56.83) v1(176.04,55.82) v1(176.46,40.56) v1(176.54,91.67) v1(176.67,40.12) v1(176.88,73.96) v1(176.88,73.33) v1(176.93,53.15) v1(177.75,71.98) v1(177.82,74.11) v1(177.82,73.47) v1(177.82,53.91) v1(177.82,51.25) v1(178.12,57.62) v1(178.19,32.42) v1(178.83,73.98) v1(178.83,73.34) v1(178.79,70.6) v1(178.96,57.64) v1(179.75,67.54) v1(179.75,66.02) v1(179.75,61.47) v1(180.53,59.2) v1(180.74,73.4) v1(180.72,53.21) v1(180.72,52.5) v1(180.72,51.79) v1(180.87,76.65) v1(180.87,76.01) v1(181.75,73.98) v1(181.75,73.34) v1(181.75,54.68) v1(181.75,53.79) v1(181.75,53.02) v1(181.75,51.75) v1(181.96,23.33) v1(182.38,81.23) v1(182.67,32.07) v1(182.6,23.33) v1(182.68,32.79) v1(182.77,73.32) v1(182.77,72.71) v1(182.77,72.07) v1(182.77,71.31) v1(182.77,51.88) v1(182.77,51.25) v1(183.23,23.33) v1(183.49,36.87) v1(183.48,32.78) v1(183.48,32.07) v1(183.66,68.39) v1(183.87,23.33) v1(184.37,32.8) v1(184.5,23.33) v1(184.6,71.44) v1(184.6,70.55) v1(184.6,69.79) v1(184.6,69.15) v1(184.57,53.21) v1(184.68,72.71) v1(184.89,31.78) v1(185.14,23.33) v1(185.26,19.66) v1(185.56,74.06) v1(185.56,72.07) v1(185.56,70.55) v1(185.56,69.79) v1(185.56,55.31) v1(185.57,54.55) v1(185.56,53.91) v1(185.56,53.16) v1(185.56,52.52) v1(185.69,94.18) v1(185.8,14.53) v1(186.08,96.85) v1(186.58,74.11) v1(186.58,72.71) v1(186.58,55.31) v1(187.55,49.26) v1(188.26,96.82) v1(188.52,71.57) v1(188.52,63.57) v1(188.52,62.72) v1(188.49,55.34) v1(188.49,53.91) v1(188.49,53.15) v1(188.49,52.5) v1(188.49,51.12) v1(188.74,90.26) v1(189.21,63.57) v1(189.5,74.18) v1(189.52,71.74) v1(189.5,69.28) v1(189.5,55.95) v1(189.5,51.12) v1(189.5,49.21) v1(189.94,63.57) v1(190.52,51.12) v1(190.9,12.81) v1(191.08,21.23) v1(191.27,89.5) v1(191.28,55.82) v1(191.41,61.66) v1(191.41,59.76) v1(191.41,51.12) v1(191.53,74.21) v1(191.53,72.07) v1(192.04,63.57) v1(192.04,59.76) v1(191.99,12.82) v1(192.17,68.39) v1(192.17,57.72) v1(192.69,92.34) v1(192.76,59.72) v1(192.8,69.41) v1(192.8,57.72) v1(192.8,56.71) v1(192.88,55.82) v1(192.96,49.25) v1(193.01,20.36) v1(193.13,13.94) v1(193.31,51.5) v1(193.44,57.72) v1(193.44,54.8) v1(193.57,52.01) v1(193.74,70.44) v1(194.07,68.39) v1(194.12,65.6) v1(194.07,64.58) v1(194.07,61.66) v1(194.15,56.78) v1(194.07,53.53) v1(194.25,59.7) v1(194.2,57.72) v1(194.2,55.82) v1(194.2,54.8) v1(194.38,73.69) v1(194.46,72.68) v1(194.44,49.23) v1(194.51,20.1) v1(195.05,49.19) v1(196.11,62.3) v1(196.11,60.66) v1(196.13,20) v1(196.54,13.86) v1(197.55,7.26) v1(197.94,94.57) v1(198.01,67.96) v1(198.07,17.58) v1(197.99,12.06) v1(198.2,93.05) v1(198.37,10.89) v1(198.52,78.93) v1(198.5,41.65) v1(198.55,17.58) v1(199.06,17.59) v1(199.39,92.02) v1(199.55,17.58) v1(199.7,7.25) v1(200.25,45.69) v1(200.25,40.81) v1(200.59,96.69) v1(200.7,27.85) v1(200.85,22.78) v1(201.08,25.84) v1(201.15,13.67) v1(201.64,10.9) v1(201.85,7.25) v1(201.92,13.02) v1(202.27,95.79) v1(202.22,12.06) v1(202.32,44.56) v1(202.28,41.83) v1(202.34,20.61) v1(202.4,18.3) v1(202.87,94.23) v1(204.34,102.6) v1(204.52,103.66) v1(204.5,21.95) v1(205.29,104.37) v1(206.15,13.23) v1(206.15,11.17) v1(206.64,20.61) v1(206.59,18.18) v1(206.77,75.5) v1(206.77,71.31) v1(206.77,67.38) v1(206.77,63.18) v1(207.41,104.37) v1(207.4,95.21) v1(207.41,75.5) v1(207.41,71.31) v1(207.41,67.38) v1(207.41,63.18) v1(208.21,103.74) v1(208.42,90.62) v1(208.56,102.6) v1(209.06,79.69) v1(211.34,11.86) v1(213.25,69.28) v1(213.38,39.82) v1(213.38,39.23) v1(214.01,89.31) v1(214.01,77.35) v1(214.01,75.55) v1(214.01,74.35) v1(214.01,72.55) v1(214.01,71.31) v1(214.01,67.75) v1(214.01,65.34) v1(214.01,62.95) v1(214.01,44.95) v1(214.08,97.15) v1(214.52,61.15) v1(214.52,53.95) v1(214.77,95.82) v1(214.77,90.55) v1(214.77,80.35) v1(214.77,40.83) v1(215.16,59.12) v1(215.28,88.47) v1(215.28,69.28) v1(215.28,49.12) v1(215.41,92.65) v1(216.3,44.05) v1(216.43,81.85) v1(217.19,75.76) v1(217.19,63.18) v1(217.82,94.45) v1(217.82,89.05) v1(217.82,80.65) v1(217.82,74.05) v1(217.82,70.45) v1(217.82,60.25) v1(217.79,57.25) v1(217.79,55.45) v1(217.82,51.85) v1(217.82,50.05) v1(217.82,47.05) v1(218.58,74.74) v1(218.58,72.85) v1(218.58,71.19) v1(218.58,69.25) v1(218.58,67.63) v1(218.58,65.72) v1(218.58,61.91) v1(220.74,37.4) v1(220.75,36.82) v1(221.06,12.99) v1(222.13,13.43) v1(223.18,41.46) v1(225.43,16.75) v1(225.91,26.78) v1(226.09,12.57) v1(226.1,12.05) v1(235.57,13.43) v1(236.05,15.44) v1(236.9,22.38) v1(239.54,23) v1(240.12,24.54) v1(240.89,21.48) v1(240.89,19.64) v1(241.03,28.88) v1(241.03,27.06) v1(242.84,25.03) v1(242.84,23.2) v2(0.77,91.88) v2(0.77,90.35) v2(0.77,87.81) v2(0.77,80.19) v2(0.77,77.65) v2(0.77,75.11) v2(0.77,72.57) v2(0.77,70.03) v2(0.77,67.49) v2(0.81,64.34) v2(0.81,61.8) v2(0.77,59.87) v2(0.77,57.33) v2(0.77,54.79) v2(0.77,52.25) v2(0.77,49.71) v2(0.77,47.17) v2(0.77,39.55) v2(0.77,37.01) v2(0.77,34.47) v2(0.77,31.93) v2(0.77,29.39) v2(0.77,26.85) v2(0.77,24.31) v2(0.77,21.77) v2(0.77,19.23) v2(0.77,16.69) v2(0.77,14.15) v2(0.77,11.61) v2(0.77,9.07) v2(0.77,7.46) v2(1.06,103.87) v2(1.04,101.33) v2(2.56,94.5) v2(2.49,10.57) v2(3.45,94.5) v2(3.89,14.08) v2(3.92,7.57) v2(5.02,82.4) v2(5.02,79.86) v2(5.02,77.32) v2(5.02,74.78) v2(5.02,72.24) v2(5.02,69.7) v2(5.06,66.54) v2(5.06,64) v2(5.02,62.08) v2(5.02,59.54) v2(5.02,57) v2(5.02,54.46) v2(5.02,51.92) v2(5.02,49.38) v2(6.22,10.53) v2(7.63,14.03) v2(7.66,7.52) v2(7.72,42.31) v2(7.72,39.77) v2(7.72,37.23) v2(7.72,34.69) v2(7.72,32.15) v2(7.72,29.61) v2(7.72,27.07) v2(7.72,24.53) v2(7.72,21.99) v2(8.76,10.53) v2(8.91,16.01) v2(10.09,78.92) v2(10.09,76.38) v2(10.09,73.84) v2(10.09,71.3) v2(10.09,68.76) v2(10.09,66.22) v2(10.13,63.07) v2(10.13,60.53) v2(10.09,58.6) v2(10.09,56.06) v2(10.09,53.52) v2(10.09,50.98) v2(10.09,48.44) v2(10.09,45.9) v2(10.18,21.74) v2(10.17,14.03) v2(10.2,7.52) v2(10.85,81.93) v2(10.84,81.01) v2(11.3,10.53) v2(12.65,15.96) v2(12.71,14.03) v2(12.74,7.52) v2(13.11,76.83) v2(13.18,45.24) v2(13.18,42.7) v2(13.18,40.16) v2(13.18,37.62) v2(13.18,35.08) v2(13.18,32.54) v2(13.18,30) v2(13.18,27.46) v2(13.18,24.92) v2(14.36,10.47) v2(14.38,94.37) v2(14.98,18.65) v2(15.14,92.26) v2(15.19,15.96) v2(15.27,94.37) v2(15.7,91.17) v2(15.77,13.98) v2(15.8,7.47) v2(16,74.62) v2(16,72.08) v2(16,69.54) v2(16,67) v2(16,64.46) v2(16.04,61.3) v2(16.04,58.76) v2(16,56.84) v2(16,54.3) v2(16,51.76) v2(16,49.22) v2(16.83,103.67) v2(16.82,101.13) v2(16.91,22.93) v2(17.77,18.68) v2(17.73,15.96) v2(18.13,91.41) v2(18.34,7.47) v2(18.9,91.41) v2(19.87,13.41) v2(20.61,76.91) v2(20.79,15.91) v2(20.88,7.47) v2(21.06,94.32) v2(21.02,18.6) v2(21.22,92.11) v2(21.22,91.35) v2(21.61,94.78) v2(21.96,90.02) v2(22.12,74.4) v2(22.12,71.86) v2(22.12,69.32) v2(22.12,66.78) v2(22.12,64.24) v2(22.16,61.08) v2(22.16,58.54) v2(22.12,56.62) v2(22.12,54.08) v2(22.12,51.54) v2(22.12,49) v2(22.62,16.64) v2(23.38,95.21) v2(23.38,94.45) v2(24.26,95.21) v2(24.26,94.45) v2(25.36,104.5) v2(25.6,13.41) v2(25.96,50.68) v2(26.13,61.63) v2(26.19,102.59) v2(26.18,54.41) v2(27.18,45.4) v2(27.44,90.26) v2(28.12,104.52) v2(28.13,102.74) v2(28.5,7.47) v2(28.72,10.19) v2(30.71,49.74) v2(30.93,74.71) v2(31.01,68.64) v2(31.44,7.41) v2(31.98,47.92) v2(33.05,54.38) v2(33.16,78.2) v2(33.16,75.66) v2(33.16,73.12) v2(33.16,70.58) v2(33.13,63.48) v2(33.19,66.46) v2(34.69,39.09) v2(34.84,64.14) v2(34.79,51.51) v2(36.06,48.03) v2(36.7,12.6) v2(37.5,87.73) v2(37.83,10.25) v2(39.06,61.11) v2(39.04,30.05) v2(39.12,58.02) v2(39.23,69.38) v2(39.17,65.6) v2(39.31,73.69) v2(39.59,15.9) v2(39.77,15.26) v2(40.5,79.09) v2(42.44,32.68) v2(43.57,104.67) v2(43.62,102.74) v2(44.14,37.64) v2(44.38,25.54) v2(45.96,97.85) v2(46.11,104.67) v2(46.34,10.62) v2(46.38,9.88) v2(46.74,97.85) v2(47.26,9.76) v2(48.05,101.39) v2(48.19,9.79) v2(48.65,104.67) v2(49.45,98.97) v2(50.16,10.61) v2(50.56,85.44) v2(50.94,10.59) v2(51.19,104.67) v2(51.3,85.45) v2(51.95,96.75) v2(52.23,101.24) v2(52.41,33.89) v2(53.73,104.67) v2(53.9,7.47) v2(54.45,68.97) v2(54.79,98.61) v2(55.2,70.14) v2(56.09,101.36) v2(56.09,32.64) v2(58.81,104.67) v2(59.07,98.04) v2(59.27,37.51) v2(61.35,104.67) v2(61.52,7.47) v2(61.68,99.89) v2(63.77,12.72) v2(63.89,104.67) v2(63.94,37.88) v2(63.87,10.71) v2(64.06,7.47) v2(64.12,97.96) v2(65.48,17.83) v2(65.76,12.61) v2(65.76,11.75) v2(66.43,104.67) v2(66.6,7.47) v2(66.71,24.43) v2(66.71,23.67) v2(67.49,56.14) v2(67.66,41.14) v2(67.81,53.4) v2(68.97,104.67) v2(69.14,7.47) v2(71.39,55.66) v2(71.51,104.67) v2(71.48,12.18) v2(71.68,7.47) v2(73.63,53.14) v2(74.05,104.67) v2(74.22,7.47) v2(74.9,23.99) v2(74.9,23.23) v2(75.78,23.99) v2(75.78,23.23) v2(76.59,104.67) v2(76.76,7.47) v2(78.14,22.36) v2(78.14,21.43) v2(78.14,20.52) v2(79.13,104.67) v2(79.3,7.47) v2(80.32,60.94) v2(81.67,104.67) v2(81.86,70.09) v2(81.84,7.47) v2(82.64,65.32) v2(83.59,101.42) v2(84.38,7.47) v2(86.02,104.66) v2(86.92,7.47) v2(89.46,7.47) v2(89.65,104.73) v2(90.09,101.36) v2(90.47,88.84) v2(91.23,7.46) v2(92.84,104.6) v2(94.51,58.78) v2(94.51,58.02) v2(94.73,99.66) v2(95.15,7.44) v2(95.2,55.47) v2(95.58,104.64) v2(97.08,7.47) v2(97.23,101.59) v2(97.23,100.7) v2(97.65,104.66) v2(98,101.59) v2(98,100.7) v2(99.62,7.47) v2(102.16,7.47) v2(103.36,22.02) v2(103.36,21.26) v2(103.75,90.26) v2(103.87,73.84) v2(103.87,73.08) v2(104.25,22.02) v2(104.25,21.26) v2(104.63,73.84) v2(104.63,73.08) v2(105.4,73.84) v2(105.4,73.08) v2(107.24,7.47) v2(107.53,104.64) v2(108.48,27.05) v2(108.48,26.29) v2(109.13,18.81) v2(109.25,27.05) v2(109.25,26.29) v2(109.61,104.67) v2(109.78,7.47) v2(110.01,27.05) v2(110.01,26.29) v2(110.77,26.29) v2(111.29,101.45) v2(111.53,26.29) v2(112.15,104.67) v2(112.36,17.96) v2(112.32,7.47) v2(112.49,101.45) v2(113.45,101.45) v2(113.82,59.66) v2(113.82,58.9) v2(113.82,58.13) v2(114.37,13.98) v2(114.58,59.66) v2(114.58,58.9) v2(114.58,58.13) v2(114.69,104.67) v2(114.77,76.28) v2(114.86,7.47) v2(116.28,76.29) v2(117.23,104.67) v2(117.28,22.73) v2(117.62,101.45) v2(119.64,76.17) v2(119.65,75.43) v2(119.75,16.86) v2(119.77,104.67) v2(120.45,79.43) v2(120.41,76.19) v2(120.41,75.43) v2(121.17,76.19) v2(121.27,67.2) v2(121.36,79.42) v2(121.96,76.19) v2(122.16,79.41) v2(122.31,104.67) v2(122.34,19.03) v2(122.34,18.01) v2(122.72,76.22) v2(123.01,67.15) v2(123.1,19.03) v2(123.1,18.01) v2(123.86,19.03) v2(123.86,18.01) v2(124.05,67.08) v2(124.85,104.67) v2(124.91,60.89) v2(125.68,60.91) v2(125.93,61.63) v2(126.35,27.66) v2(126.35,26.92) v2(126.44,60.91) v2(127.21,61.66) v2(127.17,60.91) v2(127.39,104.67) v2(127.56,7.47) v2(127.91,60.91) v2(129.25,27.61) v2(129.93,104.67) v2(129.99,27.61) v2(130.1,7.47) v2(130.65,71.31) v2(130.65,70.55) v2(130.65,69.79) v2(130.65,68.9) v2(132.28,27.3) v2(132.32,26.2) v2(132.47,104.67) v2(132.64,7.47) v2(133.05,28.22) v2(133.04,27.3) v2(133.06,26.2) v2(133.78,82.65) v2(133.99,59.73) v2(134,59.02) v2(134,58.25) v2(134.05,46.44) v2(134.05,45.68) v2(134.63,82.65) v2(135.01,104.67) v2(135.07,46.44) v2(135.07,45.68) v2(135.18,7.47) v2(136.08,46.44) v2(136.08,45.68) v2(136.69,28.1) v2(136.68,27.24) v2(137.55,104.67) v2(137.72,7.47) v2(138.63,17.18) v2(138.63,16.36) v2(138.96,76.17) v2(138.96,75.4) v2(139.39,17.18) v2(139.39,16.36) v2(139.85,76.17) v2(139.85,75.4) v2(140.09,104.67) v2(140.26,7.47) v2(140.27,90.03) v2(140.74,76.17) v2(140.74,75.4) v2(141.31,94.5) v2(141.62,76.17) v2(141.62,75.4) v2(142.51,90.05) v2(142.63,104.67) v2(142.7,94.47) v2(142.86,87.7) v2(142.8,7.47) v2(145.17,104.67) v2(146.53,43) v2(146.74,7.48) v2(147.15,27.77) v2(147.16,26.99) v2(147.11,25.37) v2(147.11,24.16) v2(147.18,67) v2(147.18,66.19) v2(147.18,65.33) v2(147.71,104.67) v2(147.96,33.51) v2(147.96,32.65) v2(147.96,31.84) v2(147.96,30.98) v2(148.31,42.74) v2(148.31,41.96) v2(148.31,41.17) v2(149.16,30.78) v2(149.16,30.02) v2(149.16,29.26) v2(149.18,31.56) v2(150.25,104.67) v2(151.9,31.13) v2(151.92,30.37) v2(152.79,104.67) v2(154.98,39.83) v2(155.33,104.67) v2(156.64,38.6) v2(156.63,37.84) v2(157.42,38.63) v2(157.41,37.85) v2(157.87,104.67) v2(160.41,104.67) v2(162.95,104.67) v2(165.49,104.67) v2(168.03,104.67) v2(168.76,13.66) v2(168.76,12.64) v2(169.71,37.79) v2(169.85,13.66) v2(169.85,12.64) v2(169.92,39.24) v2(169.92,38.49) v2(170.57,104.67) v2(170.86,13.66) v2(170.86,12.64) v2(171.72,13.78) v2(172.55,39.91) v2(172.68,13.78) v2(173.11,104.67) v2(173.57,13.78) v2(173.9,32.38) v2(173.99,28.42) v2(174.49,31.84) v2(174.65,28.07) v2(174.79,14.35) v2(175.39,13.8) v2(175.51,23.38) v2(175.65,104.67) v2(175.68,27.58) v2(176.13,84.02) v2(176.08,28.29) v2(176.22,23.75) v2(176.31,23.04) v2(176.42,27.58) v2(177.03,23.76) v2(177.16,23.04) v2(177.18,27.61) v2(177.62,40.48) v2(177.84,23.76) v2(178.05,23.04) v2(178.19,104.67) v2(178.6,23.76) v2(178.94,23.04) v2(180.57,31.81) v2(180.73,104.67) v2(181.03,32.4) v2(182.23,15.23) v2(182.23,14.47) v2(182.23,13.71) v2(183.27,104.67) v2(183.29,15.24) v2(183.29,14.48) v2(183.29,13.72) v2(184.31,15.24) v2(184.31,14.48) v2(184.31,13.72) v2(184.86,87.3) v2(185.81,104.67) v2(186.36,38) v2(186.55,41.76) v2(186.57,40.95) v2(186.56,40.16) v2(187.07,38.38) v2(187.03,37.52) v2(187.73,40.47) v2(187.72,39.68) v2(188.35,104.67) v2(188.65,94.57) v2(188.63,7.42) v2(189.83,99.44) v2(190.04,7.47) v2(190.69,19.08) v2(190.89,104.67) v2(192.58,7.47) v2(192.81,13.33) v2(193.08,19.01) v2(193.28,95.21) v2(193.43,104.67) v2(193.52,13.33) v2(194.36,7.47) v2(195.12,7.47) v2(195.96,102.73) v2(195.96,101.84) v2(195.88,7.47) v2(195.97,104.67) v2(196.45,36.6) v2(196.51,92.17) v2(196.64,7.47) v2(196.72,102.73) v2(196.72,101.84) v2(197.1,39.7) v2(197.22,96.87) v2(197.33,18.41) v2(197.94,40.46) v2(197.94,39.7) v2(198.06,19.32) v2(198.04,16.78) v2(198.04,16.02) v2(198.07,18.41) v2(198.51,104.67) v2(198.77,16.77) v2(198.77,16.01) v2(198.8,18.41) v2(199.55,18.41) v2(199.51,16.78) v2(199.51,16.02) v2(200.22,104.8) v2(200.24,46.98) v2(203.07,47.06) v2(203.08,46.22) v2(203.64,91.53) v2(204.04,12.76) v2(203.99,11.12) v2(204.25,92.09) v2(204.8,92.62) v2(205.34,93.21) v2(205.28,7.47) v2(205.45,27.58) v2(206.65,31.06) v2(207.82,7.47) v2(208.32,20.94) v2(209.56,32.86) v2(209.93,34.37) v2(210.36,7.47) v2(210.45,104.72) v2(210.6,34.96) v2(210.58,14.67) v2(210.87,32.96) v2(210.93,34.31) v2(211.33,34.96) v2(211.74,34.3) v2(211.7,24.88) v2(212.07,34.96) v2(212.56,29.63) v2(212.71,20.45) v2(212.9,7.47) v2(215.44,7.47) v2(215.9,28.55) v2(217.21,20.97) v2(217.98,7.47) v2(218.59,78.27) v2(218.9,24.96) v2(219.53,32.5) v2(220.52,11.69) v2(220.52,7.47) v2(221.37,104.67) v2(221.45,23.37) v2(221.64,92.66) v2(221.6,78.56) v2(221.71,12.95) v2(221.79,83.16) v2(221.96,87.64) v2(222.02,30.63) v2(223.06,7.47) v2(223.33,10.64) v2(223.8,102.52) v2(223.91,104.67) v2(225.27,13.33) v2(225.6,7.47) v2(226.45,104.67) v2(226.58,31.86) v2(226.9,45.98) v2(227.54,95.79) v2(227.83,99.46) v2(228.14,7.47) v2(228.8,39.45) v2(228.99,104.67) v2(230.68,7.47) v2(231.53,104.67) v2(231.85,101.95) v2(231.85,99.41) v2(231.85,96.87) v2(231.85,94.33) v2(231.85,91.79) v2(231.85,89.25) v2(231.85,86.71) v2(231.85,84.17) v2(231.85,81.63) v2(231.85,79.09) v2(231.85,76.55) v2(231.85,74.01) v2(231.85,71.47) v2(231.85,68.93) v2(231.85,66.39) v2(231.85,63.85) v2(231.85,61.31) v2(231.85,58.77) v2(231.85,56.23) v2(231.85,53.69) v2(231.85,51.15) v2(231.85,48.61) v2(231.79,32.01) v2(232.37,27.77) v2(232.37,22.44) v2(232.66,18.37) v2(233.22,7.47) v2(234,36.63) v2(234.07,104.67) v2(235.76,7.47) v2(236.23,20.28) v2(236.38,25.72) v2(236.61,104.67) v2(237.05,34.38) v2(238.3,7.47) v2(239.15,104.67) v2(239.29,102.17) v2(239.29,99.63) v2(239.29,97.09) v2(239.29,94.55) v2(239.29,92.01) v2(239.29,89.47) v2(239.29,86.93) v2(239.29,84.39) v2(239.29,81.85) v2(239.29,79.31) v2(239.29,76.77) v2(239.29,74.23) v2(239.29,71.69) v2(239.29,69.15) v2(239.29,66.61) v2(239.29,64.07) v2(239.29,61.53) v2(239.29,58.99) v2(239.29,56.45) v2(239.29,53.91) v2(239.29,51.37) v2(239.29,48.83) v2(239.29,46.29) v2(239.29,43.75) v2(239.29,41.21) v2(240.01,7.51) v2(241.69,104.67) v2(243.38,7.47) v2(244.23,104.67) v2(245.48,103.06) v2(245.48,100.52) v2(245.48,97.98) v2(245.48,95.44) v2(245.48,92.9) v2(245.48,90.36) v2(245.48,87.82) v2(245.48,85.28) v2(245.48,82.74) v2(245.48,80.2) v2(245.48,77.66) v2(245.48,75.12) v2(245.48,72.58) v2(245.48,70.04) v2(245.48,67.5) v2(245.48,64.96) v2(245.48,62.42) v2(245.48,59.88) v2(245.48,57.34) v2(245.48,54.8) v2(245.48,52.26) v2(245.48,49.72) v2(245.48,47.18) v2(245.48,44.64) v2(245.48,39.56) v2(245.48,37.02) v2(245.48,34.48) v2(245.48,31.94) v2(245.48,29.4) v2(245.48,26.86) v2(245.48,24.32) v2(245.48,21.78) v2(245.48,18.45) v2(245.48,16.77) v2(245.48,15.29) v2(245.48,11.64) v2(245.48,9.17) v2(245.48,7.51)
